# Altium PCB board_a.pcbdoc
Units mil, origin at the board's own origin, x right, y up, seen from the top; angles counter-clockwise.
Board outline 3937.01 x 4409.45 mil, 4 copper layers (Top Layer, In1.Cu, In2.Cu, Bottom Layer), stack 2.757 mil thick; 194 components, 98 nets, 535 pads, 281 vias.
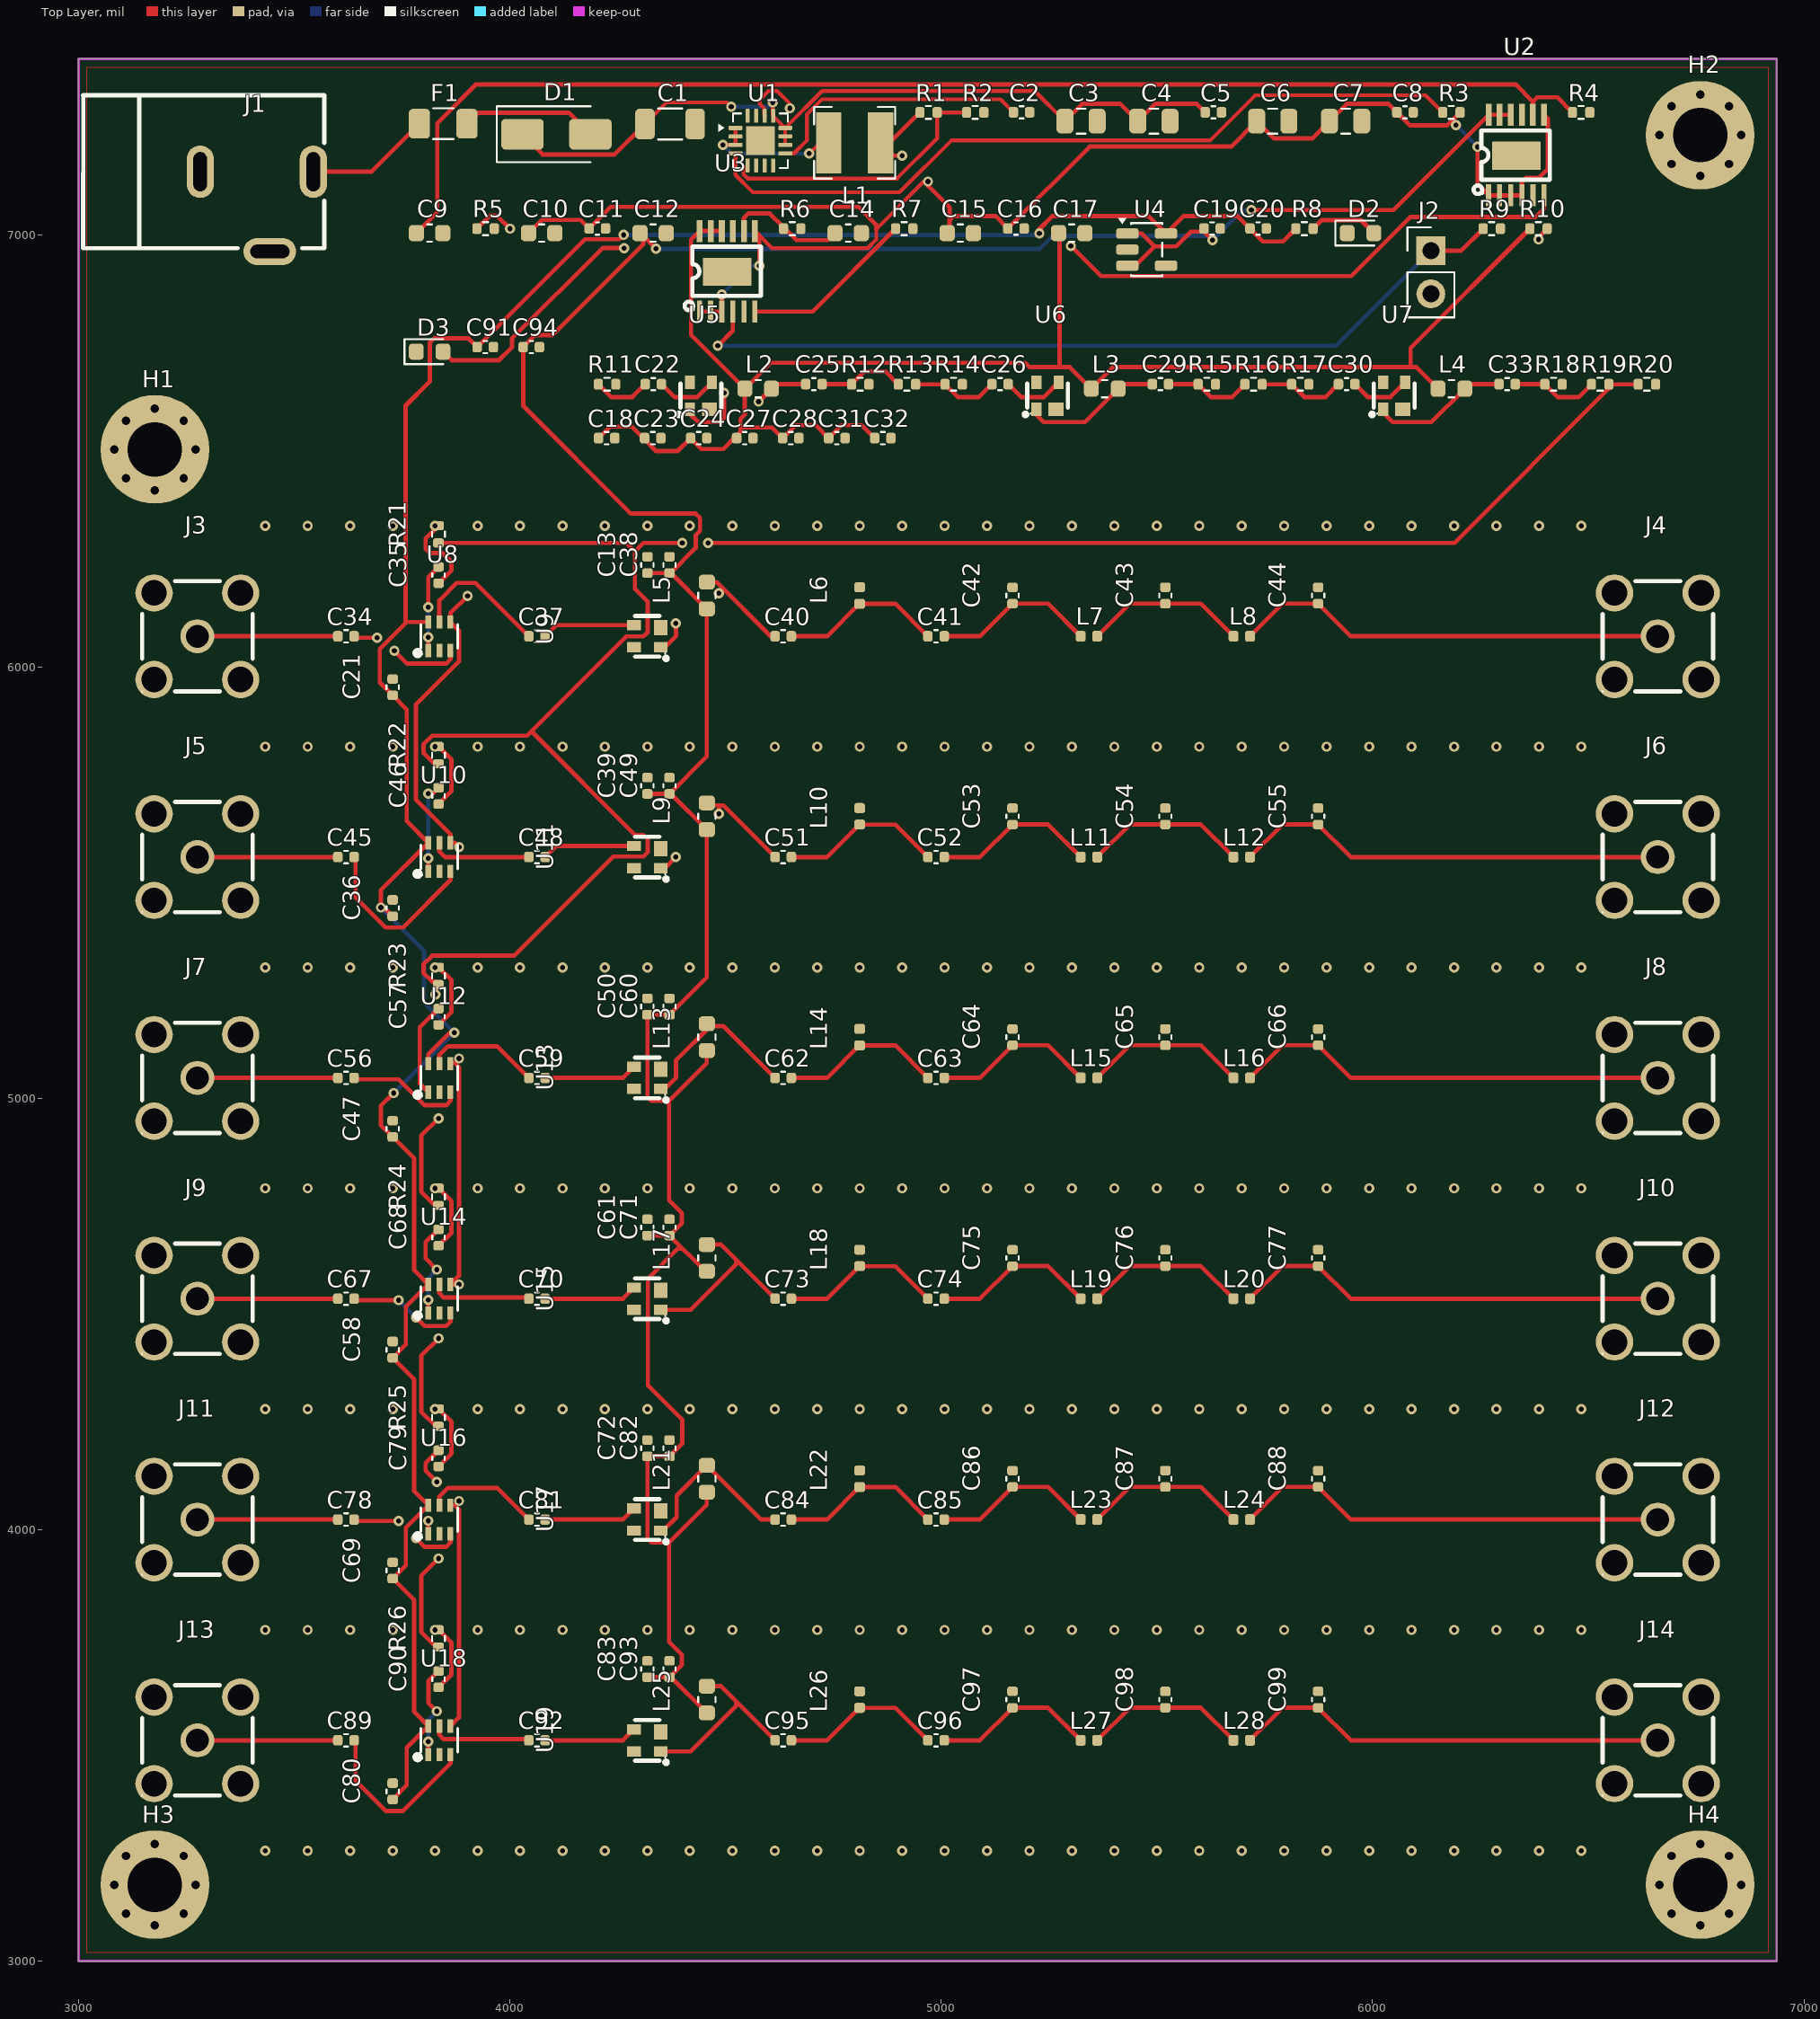
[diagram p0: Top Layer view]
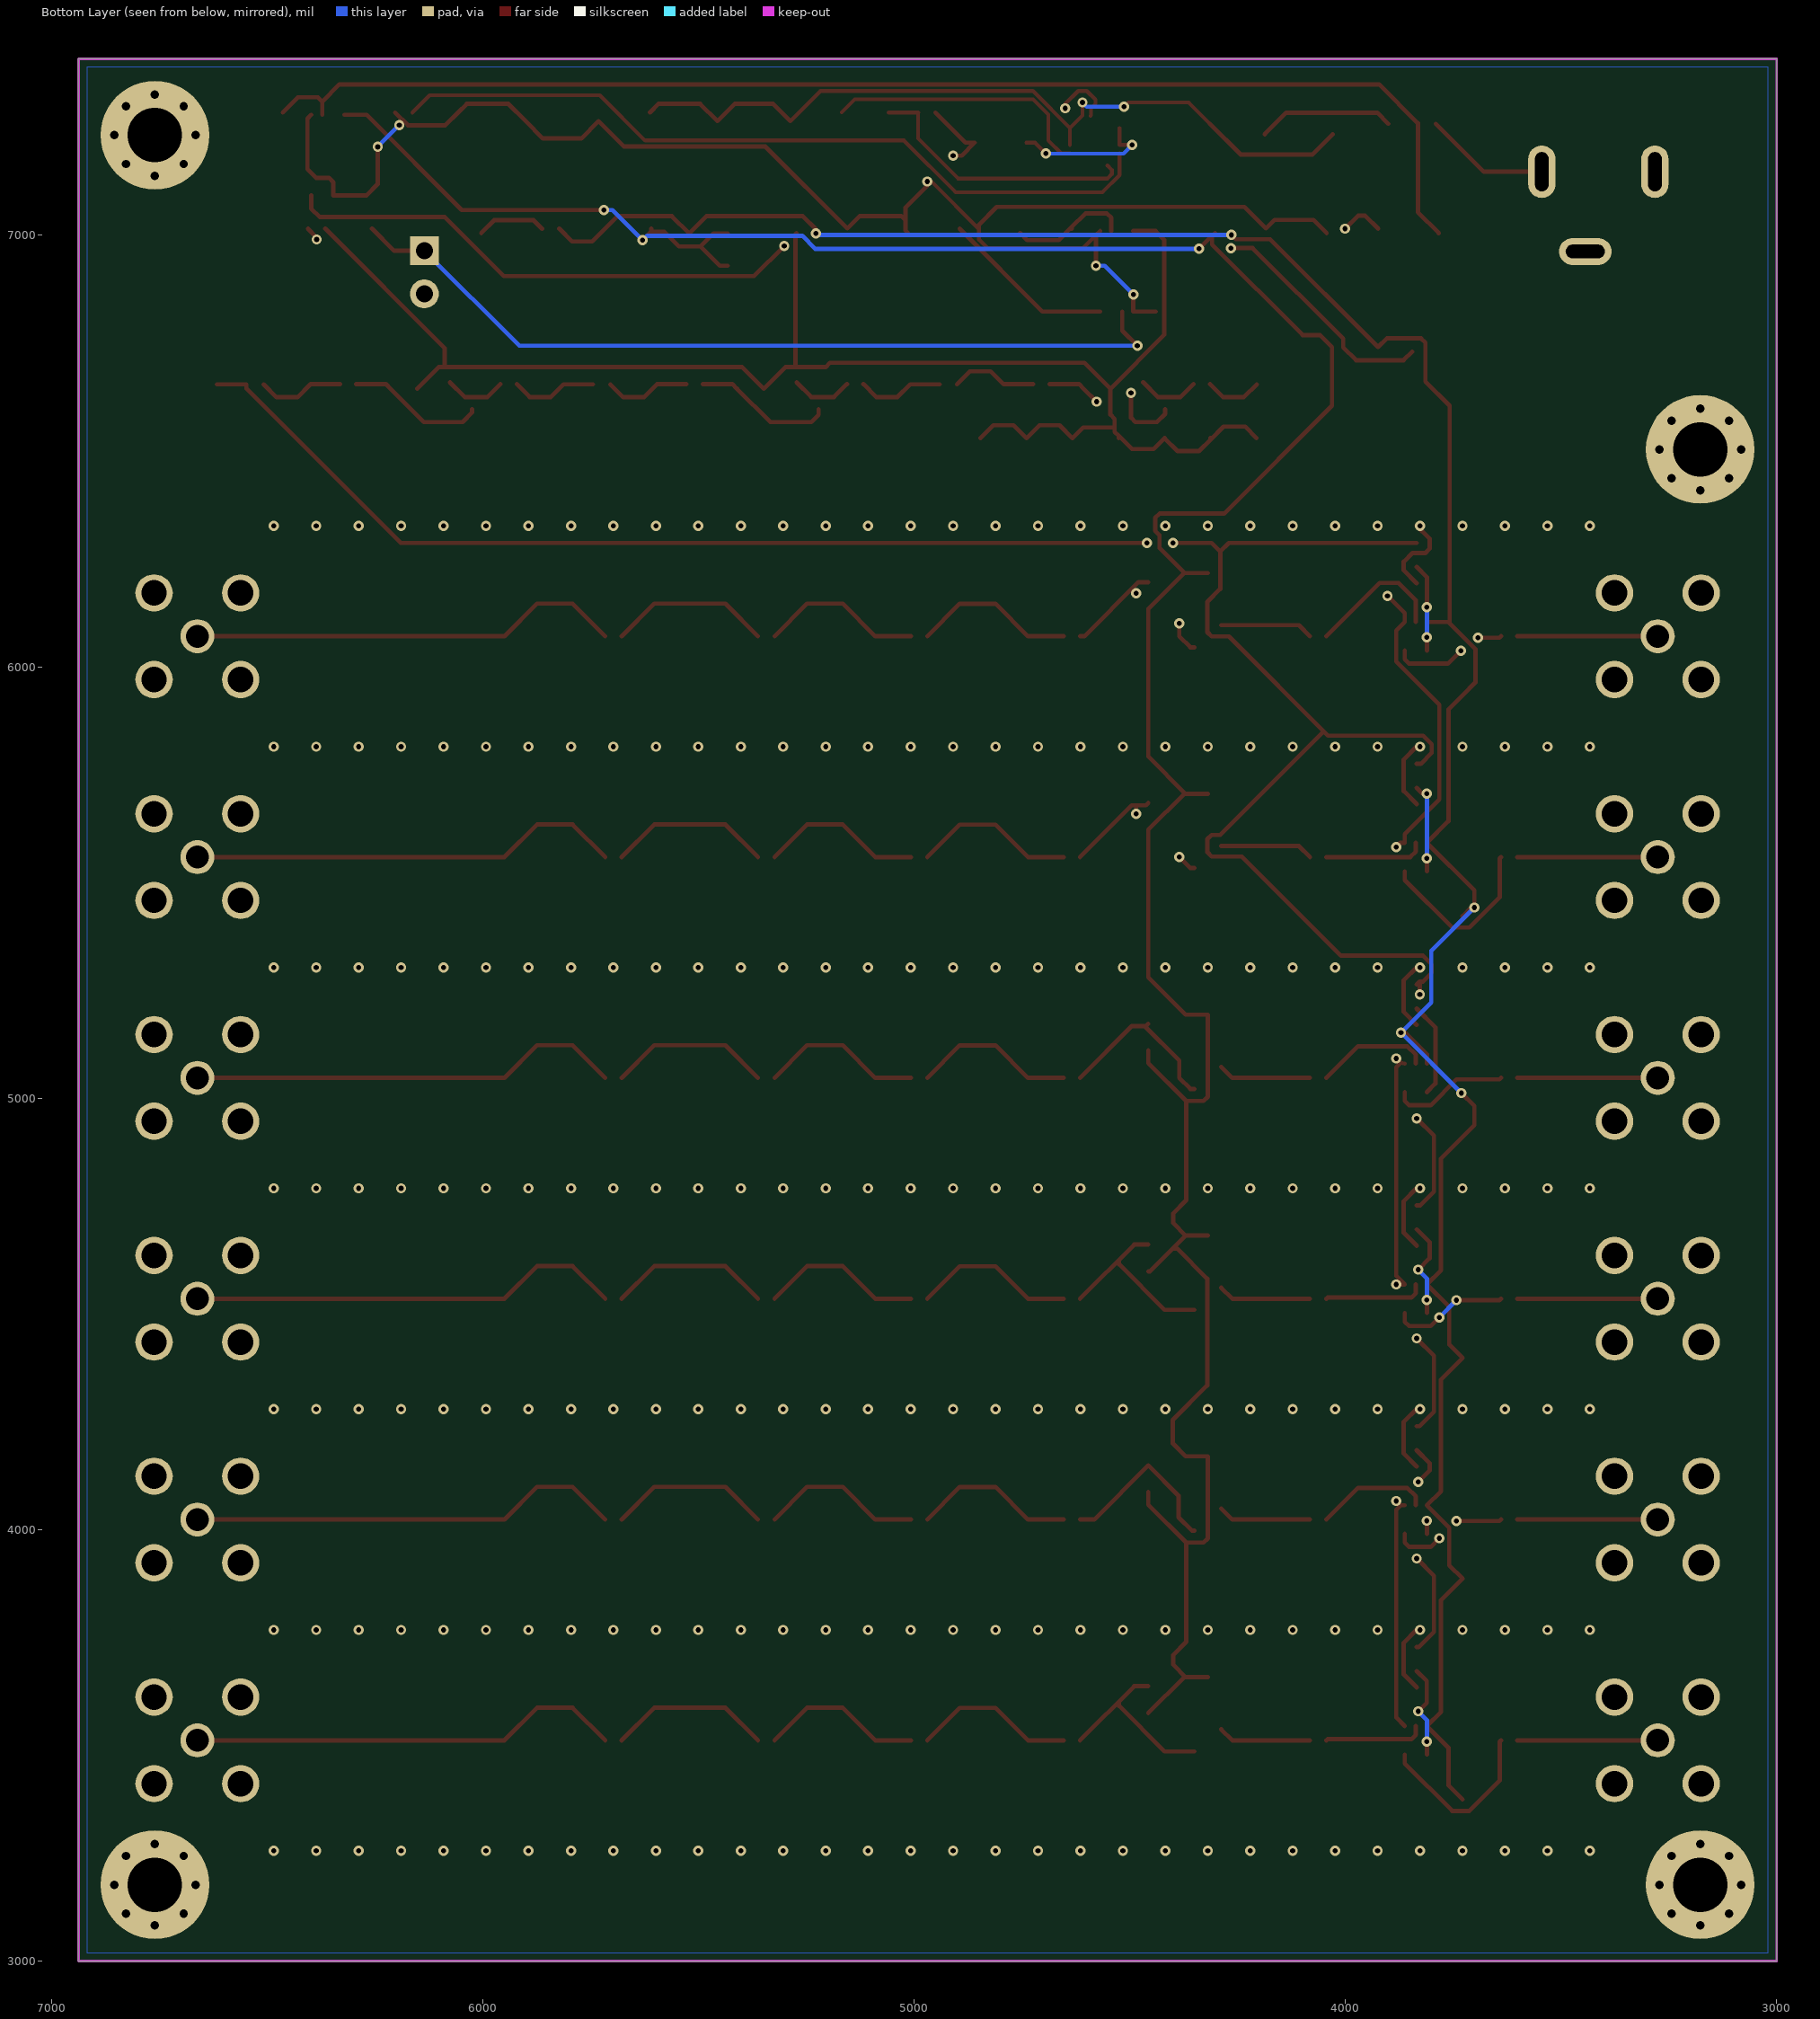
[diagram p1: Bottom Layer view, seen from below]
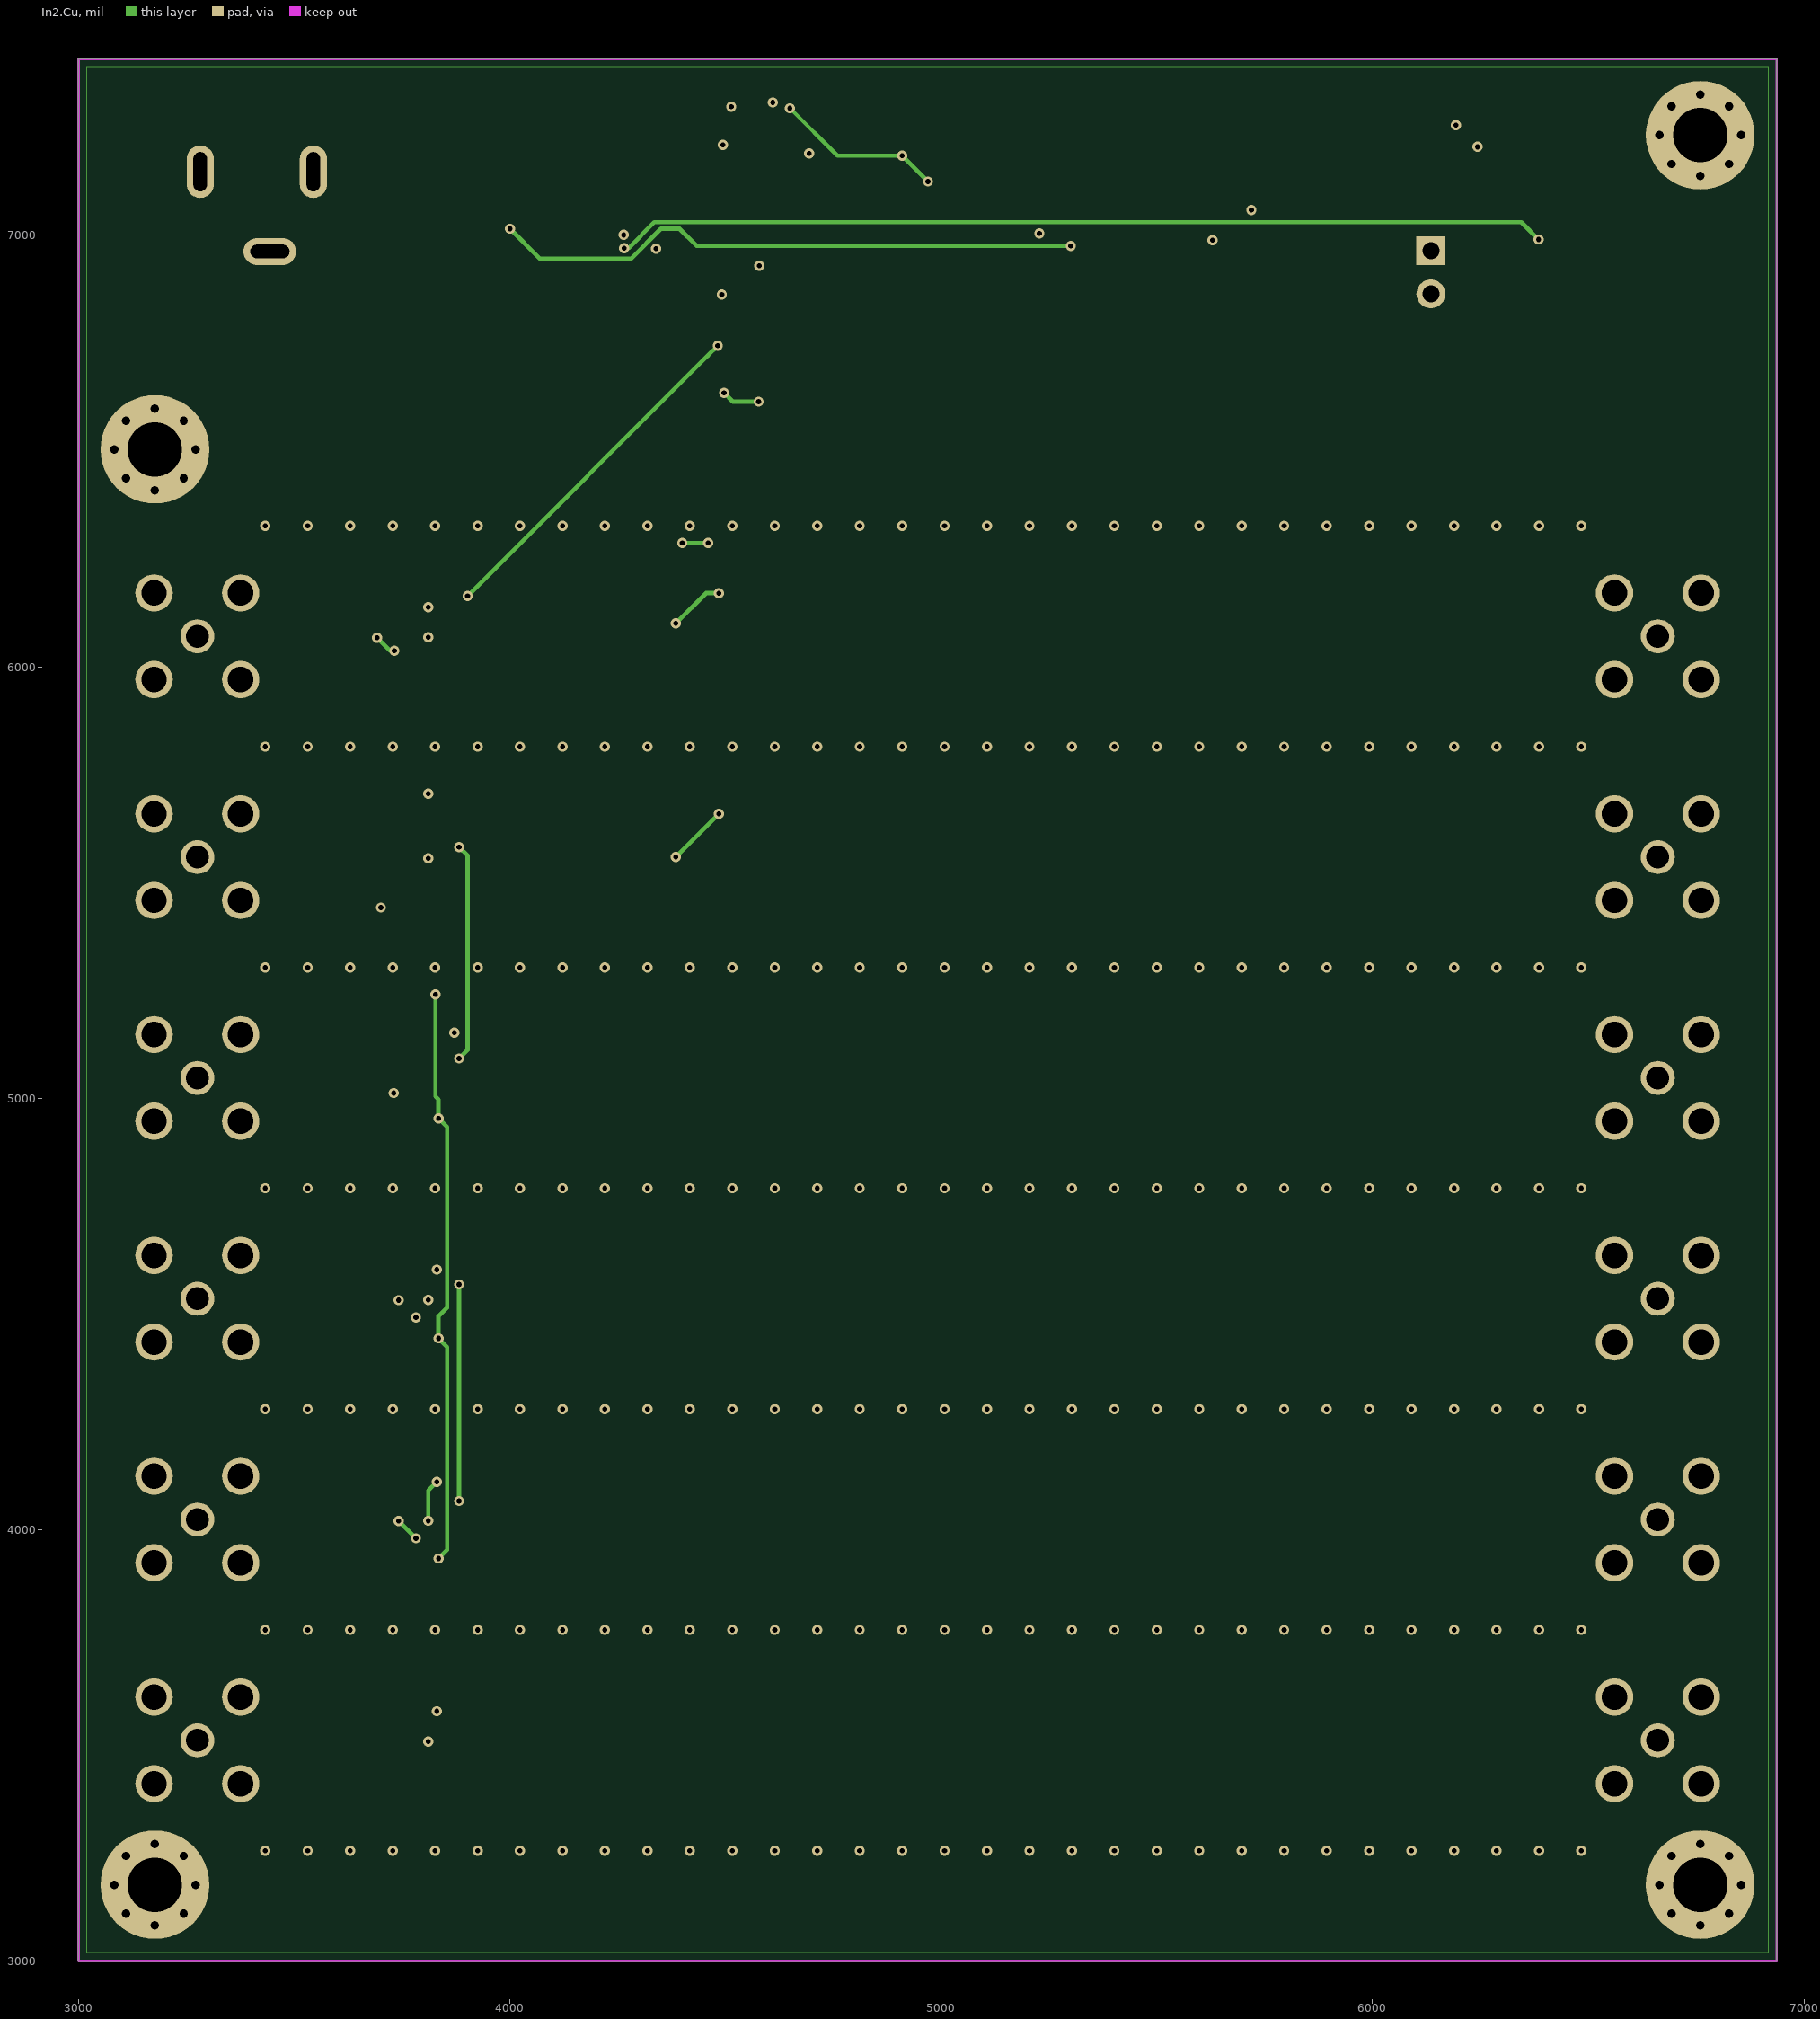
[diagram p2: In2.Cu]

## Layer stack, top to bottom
Top Solder Mask Layer: solder mask 0.394, Dk 3.3
Top Layer: signal copper 1.379
In1.Cu: signal copper (thickness not stored)
In2.Cu: signal copper (thickness not stored)
Bottom Layer: signal copper 1.378
Bottom Solder Mask Layer: solder mask 0.394, Dk 3.3

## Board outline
6937.01,3000 3000,3000 3000,7409.45 6937.01,7409.45

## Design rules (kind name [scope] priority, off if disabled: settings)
BoardOutlineClearance copperThickness1oz [All] p0: genericclearance=10 ignorepadtopadclearanceinfootprint=FALSE except(0: Arc-SplitContinuation Track-SplitContinuation SMDPad-SplitContinuation THPad-SplitContinuation Via-SplitContinuation Fill-SplitContinuation Poly-SplitContinuation Region-SplitContinuation Text-SplitContinuation)
BoardOutlineClearance otherClearance [All] p0: genericclearance=10 ignorepadtopadclearanceinfootprint=FALSE except(0: Arc-SplitContinuation Track-SplitContinuation SMDPad-SplitContinuation THPad-SplitContinuation Via-SplitContinuation Fill-SplitContinuation Poly-SplitContinuation Region-SplitContinuation Text-SplitContinuation)
Clearance copperThickness1oz [All] p1: gap=7 ignorepadtopadclearanceinfootprint=FALSE
Clearance otherClearance [All] p1: gap=7 ignorepadtopadclearanceinfootprint=FALSE
DiffPairsRouting differentialPair [All] p1: maxuncoupledlength=10 minlimit=5 maxlimit=Infinity mostfreqgap=6 toplayer_minwidth=5 toplayer_prefwidth=100 toplayer_maxwidth=100 bottomlayer_minwidth=5 bottomlayer_prefwidth=100 bottomlayer_maxwidth=100 midlayer1_minwidth=5 midlayer1_prefwidth=100 midlayer1_maxwidth=100 midlayer2_minwidth=5 midlayer2_prefwidth=100 midlayer2_maxwidth=100
PasteMaskExpansion pad_to_mask_clearance [All] p1: expansion=0
PlaneConnect innerPlane [All] p1: planeconnectstyle=Relief reliefexpansion=20 reliefentries=4 reliefconductorwidth=10 reliefairgap=10
PolygonConnect copper0 [All] p1: connectstyle=Relief reliefentries=4 reliefconductorwidth=11.811 polygonreliefangle="90 Angle" airgapwidth=9.8425
RoutingVias viaSize [All] p1: viastyle="Through Hole" holewidth=11.811 minholewidth=7.874 maxholewidth=236.2204 width=11.811 minwidth=7.874 maxwidth=236.2204
SolderMaskExpansion pad_to_mask_clearance [IsVia] p1: useseparateexpansions=TRUE expansion=-1000 expansionbottom=-1000
SolderMaskExpansion pad_to_mask_clearance [All] p2: useseparateexpansions=TRUE expansion=0 expansionbottom=0
Width copperThickness1oz [All] p1: maxlimit=100 minlimit=5 preferedwidth=10

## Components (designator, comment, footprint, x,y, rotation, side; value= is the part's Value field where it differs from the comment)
C1 "22u" Capacitor_SMD:C_1206_3216Metric 4371.46,7258.07 r0 top
C2 "3.3n" Capacitor_SMD:C_0402_1005Metric 5186.42,7285.24 r0 top
C3 "10u" Capacitor_SMD:C_0805_2012Metric 5324.21,7264.76 r0 top
C4 "10u" Capacitor_SMD:C_0805_2012Metric 5493.11,7264.76 r0 top
C5 "100n" Capacitor_SMD:C_0402_1005Metric 5630.91,7285.24 r0 top
C6 "22u" Capacitor_SMD:C_0805_2012Metric 5768.7,7264.76 r0 top
C7 "22u" Capacitor_SMD:C_0805_2012Metric 5937.6,7264.76 r0 top
C8 "100n" Capacitor_SMD:C_0402_1005Metric 6075.39,7285.24 r0 top
C9 "4.7u" Capacitor_SMD:C_0603_1608Metric 3813.98,7005.31 r0 top
C10 "10u" Capacitor_SMD:C_0603_1608Metric 4073.82,7005.31 r0 top
C11 "100n" Capacitor_SMD:C_0402_1005Metric 4202.95,7015.94 r0 top
C12 "10u" Capacitor_SMD:C_0603_1608Metric 4332.09,7005.31 r0 top
C13 "100n" Capacitor_SMD:C_0402_1005Metric 4318.9,6236.22 r90 top
C14 "4.7u" Capacitor_SMD:C_0603_1608Metric 4784.45,7005.31 r0 top
C15 "10u" Capacitor_SMD:C_0603_1608Metric 5044.29,7005.31 r0 top
C16 "100n" Capacitor_SMD:C_0402_1005Metric 5173.43,7015.94 r0 top
C17 "10u" Capacitor_SMD:C_0603_1608Metric 5302.56,7005.31 r0 top
C18 "100n" Capacitor_SMD:C_0402_1005Metric 4224.61,6530.12 r0 top
C19 "1u" Capacitor_SMD:C_0402_1005Metric 5628.15,7015.94 r0 top
C20 "1u" Capacitor_SMD:C_0402_1005Metric 5734.84,7015.94 r0 top
C21 "100n" Capacitor_SMD:C_0402_1005Metric 3728.35,5952.76 r90 top
C22 "100p" Capacitor_SMD:C_0402_1005Metric 4332.87,6655.31 r0 top
C23 "100p" Capacitor_SMD:C_0402_1005Metric 4331.3,6530.12 r0 top
C24 "100n" Capacitor_SMD:C_0402_1005Metric 4437.99,6530.12 r0 top
C25 "100p" Capacitor_SMD:C_0402_1005Metric 4704.92,6655.31 r0 top
C26 "100p" Capacitor_SMD:C_0402_1005Metric 5136.42,6655.31 r0 top
C27 "100p" Capacitor_SMD:C_0402_1005Metric 4544.69,6530.12 r0 top
C28 "100n" Capacitor_SMD:C_0402_1005Metric 4651.38,6530.12 r0 top
C29 "100p" Capacitor_SMD:C_0402_1005Metric 5508.46,6655.31 r0 top
C30 "100p" Capacitor_SMD:C_0402_1005Metric 5939.96,6655.31 r0 top
C31 "100p" Capacitor_SMD:C_0402_1005Metric 4758.07,6530.12 r0 top
C32 "100n" Capacitor_SMD:C_0402_1005Metric 4864.76,6530.12 r0 top
C33 "100p" Capacitor_SMD:C_0402_1005Metric 6312.01,6655.31 r0 top
C34 "100p" Capacitor_SMD:C_0402_1005Metric 3620.08,6070.87 r0 top
C35 "100p" Capacitor_SMD:C_0402_1005Metric 3834.65,6212.6 r90 top
C36 "100p" Capacitor_SMD:C_0402_1005Metric 3728.35,5440.94 r90 top
C37 "100p" Capacitor_SMD:C_0402_1005Metric 4062.99,6070.87 r0 top
C38 "100p" Capacitor_SMD:C_0402_1005Metric 4370.08,6236.22 r90 top
C39 "100n" Capacitor_SMD:C_0402_1005Metric 4318.9,5724.41 r90 top
C40 "7.5p" Capacitor_SMD:C_0402_1005Metric 4633.86,6070.87 r0 top
C41 "7.5p" Capacitor_SMD:C_0402_1005Metric 4988.19,6070.87 r0 top
C42 "4.7p" Capacitor_SMD:C_0402_1005Metric 5165.35,6165.35 r90 top
C43 "8.2p" Capacitor_SMD:C_0402_1005Metric 5519.69,6165.35 r90 top
C44 "4.7p" Capacitor_SMD:C_0402_1005Metric 5874.02,6165.35 r90 top
C45 "100p" Capacitor_SMD:C_0402_1005Metric 3620.08,5559.06 r0 top
C46 "100p" Capacitor_SMD:C_0402_1005Metric 3834.65,5700.79 r90 top
C47 "100p" Capacitor_SMD:C_0402_1005Metric 3728.35,4929.13 r90 top
C48 "100p" Capacitor_SMD:C_0402_1005Metric 4062.99,5559.06 r0 top
C49 "100p" Capacitor_SMD:C_0402_1005Metric 4370.08,5724.41 r90 top
C50 "100n" Capacitor_SMD:C_0402_1005Metric 4318.9,5212.6 r90 top
C51 "7.5p" Capacitor_SMD:C_0402_1005Metric 4633.86,5559.06 r0 top
C52 "7.5p" Capacitor_SMD:C_0402_1005Metric 4988.19,5559.06 r0 top
C53 "4.7p" Capacitor_SMD:C_0402_1005Metric 5165.35,5653.54 r90 top
C54 "8.2p" Capacitor_SMD:C_0402_1005Metric 5519.69,5653.54 r90 top
C55 "4.7p" Capacitor_SMD:C_0402_1005Metric 5874.02,5653.54 r90 top
C56 "100p" Capacitor_SMD:C_0402_1005Metric 3620.08,5047.24 r0 top
C57 "100p" Capacitor_SMD:C_0402_1005Metric 3834.65,5188.98 r90 top
C58 "100p" Capacitor_SMD:C_0402_1005Metric 3728.35,4417.32 r90 top
C59 "100p" Capacitor_SMD:C_0402_1005Metric 4062.99,5047.24 r0 top
C60 "100p" Capacitor_SMD:C_0402_1005Metric 4370.08,5212.6 r90 top
C61 "100n" Capacitor_SMD:C_0402_1005Metric 4318.9,4700.79 r90 top
C62 "7.5p" Capacitor_SMD:C_0402_1005Metric 4633.86,5047.24 r0 top
C63 "7.5p" Capacitor_SMD:C_0402_1005Metric 4988.19,5047.24 r0 top
C64 "4.7p" Capacitor_SMD:C_0402_1005Metric 5165.35,5141.73 r90 top
C65 "8.2p" Capacitor_SMD:C_0402_1005Metric 5519.69,5141.73 r90 top
C66 "4.7p" Capacitor_SMD:C_0402_1005Metric 5874.02,5141.73 r90 top
C67 "100p" Capacitor_SMD:C_0402_1005Metric 3620.08,4535.43 r0 top
C68 "100p" Capacitor_SMD:C_0402_1005Metric 3834.65,4677.17 r90 top
C69 "100p" Capacitor_SMD:C_0402_1005Metric 3728.35,3905.51 r90 top
C70 "100p" Capacitor_SMD:C_0402_1005Metric 4062.99,4535.43 r0 top
C71 "100p" Capacitor_SMD:C_0402_1005Metric 4370.08,4700.79 r90 top
C72 "100n" Capacitor_SMD:C_0402_1005Metric 4318.9,4188.98 r90 top
C73 "7.5p" Capacitor_SMD:C_0402_1005Metric 4633.86,4535.43 r0 top
C74 "7.5p" Capacitor_SMD:C_0402_1005Metric 4988.19,4535.43 r0 top
C75 "4.7p" Capacitor_SMD:C_0402_1005Metric 5165.35,4629.92 r90 top
C76 "8.2p" Capacitor_SMD:C_0402_1005Metric 5519.69,4629.92 r90 top
C77 "4.7p" Capacitor_SMD:C_0402_1005Metric 5874.02,4629.92 r90 top
C78 "100p" Capacitor_SMD:C_0402_1005Metric 3620.08,4023.62 r0 top
C79 "100p" Capacitor_SMD:C_0402_1005Metric 3834.65,4165.35 r90 top
C80 "100p" Capacitor_SMD:C_0402_1005Metric 3728.35,3393.7 r90 top
C81 "100p" Capacitor_SMD:C_0402_1005Metric 4062.99,4023.62 r0 top
C82 "100p" Capacitor_SMD:C_0402_1005Metric 4370.08,4188.98 r90 top
C83 "100n" Capacitor_SMD:C_0402_1005Metric 4318.9,3677.17 r90 top
C84 "7.5p" Capacitor_SMD:C_0402_1005Metric 4633.86,4023.62 r0 top
C85 "7.5p" Capacitor_SMD:C_0402_1005Metric 4988.19,4023.62 r0 top
C86 "4.7p" Capacitor_SMD:C_0402_1005Metric 5165.35,4118.11 r90 top
C87 "8.2p" Capacitor_SMD:C_0402_1005Metric 5519.69,4118.11 r90 top
C88 "4.7p" Capacitor_SMD:C_0402_1005Metric 5874.02,4118.11 r90 top
C89 "100p" Capacitor_SMD:C_0402_1005Metric 3620.08,3511.81 r0 top
C90 "100p" Capacitor_SMD:C_0402_1005Metric 3834.65,3653.54 r90 top
C91 "100p" Capacitor_SMD:C_0402_1005Metric 3943.11,6741.14 r0 top
C92 "100p" Capacitor_SMD:C_0402_1005Metric 4062.99,3511.81 r0 top
C93 "100p" Capacitor_SMD:C_0402_1005Metric 4370.08,3677.17 r90 top
C94 "100n" Capacitor_SMD:C_0402_1005Metric 4049.8,6741.14 r0 top
C95 "7.5p" Capacitor_SMD:C_0402_1005Metric 4633.86,3511.81 r0 top
C96 "7.5p" Capacitor_SMD:C_0402_1005Metric 4988.19,3511.81 r0 top
C97 "4.7p" Capacitor_SMD:C_0402_1005Metric 5165.35,3606.3 r90 top
C98 "8.2p" Capacitor_SMD:C_0402_1005Metric 5519.69,3606.3 r90 top
C99 "4.7p" Capacitor_SMD:C_0402_1005Metric 5874.02,3606.3 r90 top
D1 "SS34" Diode_SMD:D_SMA 4108.07,7234.45 r0 top
D2 "green" LED_SMD:LED_0603_1608Metric 5972.24,7005.31 r0 top
D3 "yellow" LED_SMD:LED_0603_1608Metric 3813.98,6730.51 r0 top
F1 "1.5A" Fuse:Fuse_1206_3216Metric 3845.47,7258.86 r0 top
H1 "M3" MountingHole:MountingHole_3.2mm_M3_Pad_Via 3177.17,6503.94 r0 top
H2 "M3" MountingHole:MountingHole_3.2mm_M3_Pad_Via 6759.84,7232.28 r0 top
H3 "M3" MountingHole:MountingHole_3.2mm_M3_Pad_Via 3177.17,3177.17 r0 top
H4 "M3" MountingHole:MountingHole_3.2mm_M3_Pad_Via 6759.84,3177.17 r0 top
J1 "12V DC" prc:DC-IN-TH_DC-005C-20A 3413.39,7055.12 r0 top
J2 "CAL_EN" Connector_PinHeader_2.54mm:PinHeader_1x02_P2.54mm_Vertical 6135.24,6964.37 r0 top
J3 "ANT0" prc:SMA-TH_BWSMA-KE-Z001 3275.59,6070.87 r0 top
J4 "OUT0" prc:SMA-TH_BWSMA-KE-Z001 6661.42,6070.87 r0 top
J5 "ANT1" prc:SMA-TH_BWSMA-KE-Z001 3275.59,5559.06 r0 top
J6 "OUT1" prc:SMA-TH_BWSMA-KE-Z001 6661.42,5559.06 r0 top
J7 "ANT2" prc:SMA-TH_BWSMA-KE-Z001 3275.59,5047.24 r0 top
J8 "OUT2" prc:SMA-TH_BWSMA-KE-Z001 6661.42,5047.24 r0 top
J9 "ANT3" prc:SMA-TH_BWSMA-KE-Z001 3275.59,4535.43 r0 top
J10 "OUT3" prc:SMA-TH_BWSMA-KE-Z001 6661.42,4535.43 r0 top
J11 "ANT4" prc:SMA-TH_BWSMA-KE-Z001 3275.59,4023.62 r0 top
J12 "OUT4" prc:SMA-TH_BWSMA-KE-Z001 6661.42,4023.62 r0 top
J13 "ANT5" prc:SMA-TH_BWSMA-KE-Z001 3275.59,3511.81 r0 top
J14 "OUT5" prc:SMA-TH_BWSMA-KE-Z001 6661.42,3511.81 r0 top
L1 "2.2u" Inductor_SMD:L_Bourns-SRN4018 4799.41,7214.76 r0 top
L2 "220n" Inductor_SMD:L_0603_1608Metric 4575.79,6644.69 r0 top
L3 "220n" Inductor_SMD:L_0603_1608Metric 5379.33,6644.69 r0 top
L4 "220n" Inductor_SMD:L_0603_1608Metric 6182.87,6644.69 r0 top
L5 "220n" Inductor_SMD:L_0603_1608Metric 4456.69,6165.35 r90 top
L6 "15n" Inductor_SMD:L_0402_1005Metric 4811.02,6165.35 r90 top
L7 "15n" Inductor_SMD:L_0402_1005Metric 5342.52,6070.87 r0 top
L8 "15n" Inductor_SMD:L_0402_1005Metric 5696.85,6070.87 r0 top
L9 "220n" Inductor_SMD:L_0603_1608Metric 4456.69,5653.54 r90 top
L10 "15n" Inductor_SMD:L_0402_1005Metric 4811.02,5653.54 r90 top
L11 "15n" Inductor_SMD:L_0402_1005Metric 5342.52,5559.06 r0 top
L12 "15n" Inductor_SMD:L_0402_1005Metric 5696.85,5559.06 r0 top
L13 "220n" Inductor_SMD:L_0603_1608Metric 4456.69,5141.73 r90 top
L14 "15n" Inductor_SMD:L_0402_1005Metric 4811.02,5141.73 r90 top
L15 "15n" Inductor_SMD:L_0402_1005Metric 5342.52,5047.24 r0 top
L16 "15n" Inductor_SMD:L_0402_1005Metric 5696.85,5047.24 r0 top
L17 "220n" Inductor_SMD:L_0603_1608Metric 4456.69,4629.92 r90 top
L18 "15n" Inductor_SMD:L_0402_1005Metric 4811.02,4629.92 r90 top
L19 "15n" Inductor_SMD:L_0402_1005Metric 5342.52,4535.43 r0 top
L20 "15n" Inductor_SMD:L_0402_1005Metric 5696.85,4535.43 r0 top
L21 "220n" Inductor_SMD:L_0603_1608Metric 4456.69,4118.11 r90 top
L22 "15n" Inductor_SMD:L_0402_1005Metric 4811.02,4118.11 r90 top
L23 "15n" Inductor_SMD:L_0402_1005Metric 5342.52,4023.62 r0 top
L24 "15n" Inductor_SMD:L_0402_1005Metric 5696.85,4023.62 r0 top
L25 "220n" Inductor_SMD:L_0603_1608Metric 4456.69,3606.3 r90 top
L26 "15n" Inductor_SMD:L_0402_1005Metric 4811.02,3606.3 r90 top
L27 "15n" Inductor_SMD:L_0402_1005Metric 5342.52,3511.81 r0 top
L28 "15n" Inductor_SMD:L_0402_1005Metric 5696.85,3511.81 r0 top
R1 "600k" Resistor_SMD:R_0402_1005Metric 4970.67,7284.84 r0 top
R2 "100k" Resistor_SMD:R_0402_1005Metric 5078.94,7284.84 r0 top
R3 "100k" Resistor_SMD:R_0402_1005Metric 6182.87,7284.84 r0 top
R4 "50.0k" Resistor_SMD:R_0402_1005Metric 6483.66,7284.84 r0 top
R5 "300" Resistor_SMD:R_0402_1005Metric 3943.9,7015.55 r0 top
R6 "50.0k" Resistor_SMD:R_0402_1005Metric 4654.53,7015.55 r0 top
R7 "300" Resistor_SMD:R_0402_1005Metric 4914.37,7015.55 r0 top
R8 "4.7k" Resistor_SMD:R_0402_1005Metric 5842.32,7015.55 r0 top
R9 "100k" Resistor_SMD:R_0402_1005Metric 6276.57,7015.55 r0 top
R10 "4.7k" Resistor_SMD:R_0402_1005Metric 6384.84,7015.55 r0 top
R11 "49.9" Resistor_SMD:R_0402_1005Metric 4225.39,6654.92 r0 top
R12 "294" Resistor_SMD:R_0402_1005Metric 4812.4,6654.92 r0 top
R13 "17.8" Resistor_SMD:R_0402_1005Metric 4920.67,6654.92 r0 top
R14 "294" Resistor_SMD:R_0402_1005Metric 5028.94,6654.92 r0 top
R15 "294" Resistor_SMD:R_0402_1005Metric 5615.94,6654.92 r0 top
R16 "17.8" Resistor_SMD:R_0402_1005Metric 5724.21,6654.92 r0 top
R17 "294" Resistor_SMD:R_0402_1005Metric 5832.48,6654.92 r0 top
R18 "294" Resistor_SMD:R_0402_1005Metric 6419.49,6654.92 r0 top
R19 "17.8" Resistor_SMD:R_0402_1005Metric 6527.76,6654.92 r0 top
R20 "294" Resistor_SMD:R_0402_1005Metric 6636.02,6654.92 r0 top
R21 "35.7" Resistor_SMD:R_0402_1005Metric 3834.65,6307.09 r90 top
R22 "35.7" Resistor_SMD:R_0402_1005Metric 3834.65,5795.28 r90 top
R23 "35.7" Resistor_SMD:R_0402_1005Metric 3834.65,5283.46 r90 top
R24 "35.7" Resistor_SMD:R_0402_1005Metric 3834.65,4771.65 r90 top
R25 "35.7" Resistor_SMD:R_0402_1005Metric 3834.65,4259.84 r90 top
R26 "35.7" Resistor_SMD:R_0402_1005Metric 3834.65,3748.03 r90 top
U1 "TPS62130RGTR" Package_DFN_QFN:VQFN-16-1EP_3x3mm_P0.5mm_EP1.68x1.68mm 4580.91,7219.49 r0 top
U2 "LT3045EMSE" prc:MSOP-12_L4.0-W3.0-P0.65-LS4.9-BL-EP 6333.27,7186.22 r0 top
U3 "LT3045EMSE" prc:MSOP-12_L4.0-W3.0-P0.65-LS4.9-BL-EP 4504.13,6916.93 r0 top
U4 "TLV75533PDBVR" Package_TO_SOT_SMD:SOT-23-5 5476.57,6967.13 r0 top
U5 "SPF5043Z" prc:SOT343_L2.0-W1.3-P1.30-LS2.1-BL 4443.11,6628.35 r0 top
U6 "SPF5043Z" prc:SOT343_L2.0-W1.3-P1.30-LS2.1-BL 5246.65,6628.35 r0 top
U7 "SPF5043Z" prc:SOT343_L2.0-W1.3-P1.30-LS2.1-BL 6050.2,6628.35 r0 top
U8 "PE4259-63" prc:SC-70-6_L2.2-W1.3-P0.65-LS2.1-BL 3836.61,6070.87 r0 top
U9 "SPF5043Z" prc:SOT343_L2.0-W1.3-P1.30-LS2.1-BL 4318.9,6070.87 r90 top
U10 "PE4259-63" prc:SC-70-6_L2.2-W1.3-P0.65-LS2.1-BL 3836.61,5559.06 r0 top
U11 "SPF5043Z" prc:SOT343_L2.0-W1.3-P1.30-LS2.1-BL 4318.9,5559.06 r90 top
U12 "PE4259-63" prc:SC-70-6_L2.2-W1.3-P0.65-LS2.1-BL 3836.61,5047.24 r0 top
U13 "SPF5043Z" prc:SOT343_L2.0-W1.3-P1.30-LS2.1-BL 4318.9,5047.24 r90 top
U14 "PE4259-63" prc:SC-70-6_L2.2-W1.3-P0.65-LS2.1-BL 3836.61,4535.43 r0 top
U15 "SPF5043Z" prc:SOT343_L2.0-W1.3-P1.30-LS2.1-BL 4318.9,4535.43 r90 top
U16 "PE4259-63" prc:SC-70-6_L2.2-W1.3-P0.65-LS2.1-BL 3836.61,4023.62 r0 top
U17 "SPF5043Z" prc:SOT343_L2.0-W1.3-P1.30-LS2.1-BL 4318.9,4023.62 r90 top
U18 "PE4259-63" prc:SC-70-6_L2.2-W1.3-P0.65-LS2.1-BL 3836.61,3511.81 r0 top
U19 "SPF5043Z" prc:SOT343_L2.0-W1.3-P1.30-LS2.1-BL 4318.9,3511.81 r90 top

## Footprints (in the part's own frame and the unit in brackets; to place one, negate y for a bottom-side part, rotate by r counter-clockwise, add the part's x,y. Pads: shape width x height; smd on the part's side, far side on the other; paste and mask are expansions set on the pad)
Capacitor_SMD:C_0402_1005Metric [mm]
  rrect50% 0.56x0.62 smd: 1(-0.48,0) 2(0.48,0)
  silkscreen extent -0.11,-0.36 0.11,0.36
Capacitor_SMD:C_0603_1608Metric [mm]
  rrect50% 0.9x0.95 smd: 1(-0.775,0) 2(0.775,0)
  silkscreen extent -0.14,-0.51 0.14,0.51
Capacitor_SMD:C_0805_2012Metric [mm]
  rrect50% 1x1.45 smd: 1(-0.95,0) 2(0.95,0)
  silkscreen extent -0.26,-0.73 0.26,0.73
Capacitor_SMD:C_1206_3216Metric [mm]
  rrect43% 1.15x1.8 smd: 1(-1.475,0) 2(1.475,0)
  silkscreen extent -0.71,-0.91 0.71,0.91
Connector_PinHeader_2.54mm:PinHeader_1x02_P2.54mm_Vertical [mm]
  rect 1.7x1.7 hole 1: 1(0,0)
  round 1.7 hole 1: 2(0,-2.54)
  silkscreen extent -1.38,-3.92 1.38,1.38
Diode_SMD:D_SMA [mm]
  rrect27% 2.5x1.8 smd: 1(-2,0) 2(2,0)
  silkscreen extent -3.51,-1.65 2,1.65
Fuse:Fuse_1206_3216Metric [mm]
  rrect40% 1.25x1.75 smd: 1(-1.4,0) 2(1.4,0)
  silkscreen extent -0.6,-0.91 0.6,0.91
Inductor_SMD:L_0402_1005Metric [mm]
  rrect50% 0.59x0.64 smd: 1(-0.485,0) 2(0.485,0)
Inductor_SMD:L_0603_1608Metric [mm]
  rrect50% 0.875x0.95 smd: 1(-0.787,0) 2(0.787,0)
  silkscreen extent -0.16,-0.51 0.16,0.51
Inductor_SMD:L_Bourns-SRN4018 [mm]
  rect 1.5x3.6 smd: 1(-1.525,0) 2(1.525,0)
  silkscreen extent -2.38,-2.11 2.39,2.11
LED_SMD:LED_0603_1608Metric [mm]
  rrect50% 0.875x0.95 smd: 1(-0.788,0) 2(0.787,0)
  silkscreen extent -1.49,-0.73 0.8,0.73
MountingHole:MountingHole_3.2mm_M3_Pad_Via [mm]
  round 0.8 hole 0.5: 1(-2.4,0) 1(-1.697,-1.697) 1(-1.697,1.697) 1(0,-2.4) 1(0,2.4) 1(1.697,-1.697) 1(1.697,1.697) 1(2.4,0)
  round 6.4 hole 3.2: 1(0,0)
Package_DFN_QFN:VQFN-16-1EP_3x3mm_P0.5mm_EP1.68x1.68mm [mm]
  rrect50% 0.825x0.25 smd: 1(-1.462,0.75) 2(-1.462,0.25) 3(-1.462,-0.25) 4(-1.462,-0.75) 9(1.463,-0.75) 10(1.463,-0.25) 11(1.463,0.25) 12(1.463,0.75)
  rrect50% 0.25x0.825 smd: 5(-0.75,-1.462) 6(-0.25,-1.462) 7(0.25,-1.462) 8(0.75,-1.462) 13(0.75,1.462) 14(0.25,1.462) 15(-0.25,1.462) 16(-0.75,1.462)
  rect 1.68x1.68 smd: 17(0,0)
  silkscreen extent -2.47,-1.61 1.61,1.61
Package_TO_SOT_SMD:SOT-23-5 [mm]
  rrect50% 1.325x0.6 smd: 1(-1.138,0.95) 2(-1.138,0) 3(-1.138,-0.95) 4(1.138,-0.95) 5(1.138,0.95)
  silkscreen extent -1.69,-1.56 0.91,1.84
prc:DC-IN-TH_DC-005C-20A [mm]
  oval 1.6x3.1 hole 0.8 slot 2.3 at 90 deg: 1(3.33,2.35) 2(-3.33,2.35)
  oval 3.1x1.6 hole 0.8 slot 2.3 at 0 deg: 3(0.77,-2.35)
  silkscreen extent -10.23,-2.15 4.01,6.88
prc:MSOP-12_L4.0-W3.0-P0.65-LS4.9-BL-EP [mm]
  rect 0.3x1.3 smd: 1(-1.63,-2.37) 2(-0.98,-2.37) 3(-0.32,-2.37) 4(0.33,-2.37) 5(0.98,-2.37) 6(1.63,-2.37)
  rect 0.35x1.3 smd: 7(1.63,2.37) 8(0.98,2.37) 9(0.33,2.37) 10(-0.32,2.37) 11(-0.98,2.37) 12(-1.63,2.37)
  rect 2.85x1.65 smd: 13(0,-0.04)
  silkscreen extent -2.51,-2.3 1.98,1.45
prc:SC-70-6_L2.2-W1.3-P0.65-LS2.1-BL [mm]
  rect 0.35x0.78 smd: 1(-0.65,-0.84) 2(0,-0.84) 3(0.65,-0.84) 4(0.65,0.84) 5(0,0.84) 6(-0.65,0.84)
  silkscreen extent -1.43,-1.14 1.08,0.7
prc:SMA-TH_BWSMA-KE-Z001 [mm]
  round 2.2 hole 1.5: 1(-2.55,-2.55) 2(-2.55,2.55) 3(2.55,2.55) 4(2.55,-2.55)
  round 2 hole 1.35: 5(0,0)
  silkscreen extent -3.28,-3.28 3.25,3.25
prc:SOT343_L2.0-W1.3-P1.30-LS2.1-BL [mm]
  rect 0.599x0.8 smd: 1(-0.65,-0.79) 3(0.65,0.79) 4(-0.65,0.79)
  rect 0.899x0.8 smd: 2(0.5,-0.79)
  silkscreen extent -1.4,-1.2 1.2,0.72
Resistor_SMD:R_0402_1005Metric [mm]
  rrect50% 0.54x0.64 smd: 1(-0.51,0) 2(0.51,0)
  silkscreen extent -0.15,-0.38 0.15,0.38

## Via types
v1: diameter 23.62, hole 11.8, Top Layer to Bottom Layer, 281 vias

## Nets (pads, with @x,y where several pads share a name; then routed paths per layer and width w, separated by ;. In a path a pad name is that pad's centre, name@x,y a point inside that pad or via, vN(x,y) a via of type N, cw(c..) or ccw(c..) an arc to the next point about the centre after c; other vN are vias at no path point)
+3V3: C20.1 C21.1 C36.1 C47.1 C58.1 C69.1 C80.1 C91.1 R8.1 U4.5 U8.6 U10.6 U12.6 U14.6 U16.6 U18.6 | length 6287.9
  Top Layer w10: C80.1 3761.02,3407.48 3761.02,3494.88 U18.6 3778.34,3577.56 3778.34,3836.61 C69.1 3759.01,3917.28 3759.01,4004.68 U16.6 3778.34,4089.37 3778.34,4348.42 C58.1 3759.01,4429.09 3759.01,4516.5 U14.6 3778.34,4601.18 3778.34,4860.24 C47.1 3701.02,4937.56 3701.02,4982.13 v1(3731.02,5012.13) ; C36.1 3708.27,5442.13 v1(3701.02,5442.13) 3701.02,5482.13 U10.6 3761.02,5642.13 3761.02,5901.18 C21.1 3698.35,5963.86 3698.35,6041.26 3761.02,6103.94 U8.6 ; 3758.34,6101.26 3758.34,6605.28 3814.33,6661.26 3814.33,6751.26 3824.33,6761.26 3904.1,6761.26 C91.1 4174.21,6991.14 4254.21,6991.14 v1(4264.21,7001.14) ; U12.6 3811.02,5102.13 3861.02,5152.13 v1(3871.02,5152.13) ; v1(5227.59,7004.53) 5227.59,7014.53 5257.59,7044.53 5481.36,7044.53 U4.5 5561.36,7044.53 5687.36,7044.53 C20.1 5745.94,6985.95 5792.64,6985.95 R8.1
  Bottom Layer w10: v1(3701.02,5442.13) 3801.02,5342.13 3801.02,5222.13 3866.7,5156.45 v1(3871.02,5152.13) v1(3731.02,5012.13) ; v1(4264.21,7001.14) 5224.21,7001.14 v1(5227.59,7004.53)
+5V6: C6.1 C7.1 C8.1 C10.1 C11.1 C15.1 C16.1 L1.2 R1.1 R3.2 U1.14 U2.1 U2.2 U2.3 U2.4 U2.7 U3.1 U3.2 U3.3 U3.7 | length 4422.4
  Top Layer w8.89: U3.7 4608.31,6970.24 4829.45,6970.24 4849.45,6990.24 4849.45,7014.76 4959.45,7124.76 v1(4969.45,7124.76) ; U1.14 4589.45,7278.37 4589.45,7294.76 4579.45,7304.76 4579.45,7314.76 4599.45,7334.76 4619.45,7334.76 4649.45,7304.76 v1(4649.45,7294.76)
  Top Layer w10: C10.1 4073.94,7035.95 4164.06,7035.95 C11.1 4234.06,7065.95 4808.27,7065.95 4849.45,7024.76 4849.45,7014.76 ; U3.1 U3.2 U3.3 v1(4491.54,6862.88) ; U3.7 4578.31,7000.24 v1(4578.31,6929.65) ; v1(4909.45,7184.76) 4889.45,7184.76 L1.2 4880.51,7214.76 R1.1 ; v1(4969.45,7124.76) 4969.45,7114.76 5019.45,7064.76 5019.45,7010.98 C15.1 ; 5019.45,7034.76 5029.45,7044.76 5125.71,7044.76 C16.1 5344.53,7205.95 5672.48,7205.95 C6.1 5771.3,7224.76 5860.2,7224.76 C7.1 5940.19,7304.76 6036.97,7304.76 C8.1 6086.5,7255.24 6173.35,7255.24 R3.2 ; 6183.35,7265.24 v1(6193.35,7255.24) ; v1(6243.35,7205.24) 6243.35,7118.66 U2.1 U2.2 U2.3 U2.4 6346.26,7123.5 6356.26,7133.5 6386.26,7133.5 6406.26,7153.5 6406.26,7270.71 U2.7
  In2.Cu w8.89: v1(4649.45,7294.76) 4759.45,7184.76 v1(4909.45,7184.76)
  In2.Cu w10: v1(4909.45,7184.76) v1(4969.45,7124.76)
  Bottom Layer w10: v1(4491.54,6862.88) 4558.31,6929.65 v1(4578.31,6929.65) ; v1(6193.35,7255.24) v1(6243.35,7205.24)
+5V_LNA: C12.1 C13.1 C19.1 C38.1 C39.1 C49.1 C50.1 C60.1 C61.1 C71.1 C72.1 C82.1 C83.1 C93.1 C94.1 L5.1 L9.1 L13.1 L17.1 L21.1 L25.1 U2.10 U2.11 U2.12 U4.1 U4.3 | length 7452.1
  Top Layer w10: C12.1 C12.1@4309.1,6998.94 ; C83.1 C93.1 ; C61.1 C71.1 ; C39.1 C49.1 ; C13.1 C38.1@4372.91,6217.32 ; v1(4339.1,6968.94) C12.1@4309.1,6998.94 ; 4400.08,4651.89 4390.08,4651.89 4320.08,4581.89 4320.08,4334.41 4400.08,4254.41 4400.08,4200.08 C82.1 C72.1 4318.9,3980.08 4328.9,3970.08 4368.9,3970.08 ; L25.1 4373.72,3658.27 C93.1 ; L21.1 4456.69,4057.87 4368.9,3970.08 ; L17.1 4453.05,4598.92 C71.1 ; L13.1 4456.69,5081.5 4368.9,4993.7 ; U4.3 5449.88,6929.73 5494.69,6974.53 ; U4.1 5464.69,7004.53 5494.69,6974.53 ; C19.1 C19.1@5609.1,7008.94 ; v1(5629.1,6988.94) C19.1@5609.1,7008.94 ; v1(5719.1,7058.94) 6048.51,7058.94 U2.12 U2.11 U2.10 ; C12.1@4309.1,6998.94 4309.1,6978.94 4099.1,6768.94 4058.7,6768.94 C94.1 4030.91,6605.31 4280.91,6355.31 4430.91,6355.31 4440.91,6345.31 4440.91,6315.31 4430.91,6305.31 4430.91,6275.31 C38.1@4372.91,6217.32 ; 4368.9,3970.08 4368.9,3740.08 4398.9,3710.08 4398.9,3687.09 C93.1 ; 4368.9,4993.7 4328.9,4993.7 4318.9,5003.7 C50.1 C60.1 4456.69,5280.32 L9.1 4373.72,5705.51 C49.1 ; 4368.9,4993.7 4368.9,4763.7 4398.9,4733.7 4398.9,4710.71 C71.1 ; C49.1 4456.69,5792.13 4456.69,6134.35 4373.72,6217.32 C38.1@4372.91,6217.32 ; 5494.69,6974.53 5544.69,6974.53 5579.1,7008.94 C19.1@5609.1,7008.94
  Bottom Layer w10: v1(4339.1,6968.94) 5229.1,6968.94 5259.1,6998.94 5619.1,6998.94 v1(5629.1,6988.94) 5659.1,7018.94 5699.1,7058.94 v1(5719.1,7058.94)
+5V_NS: C17.1 C18.1 C23.1 C24.1 C27.1 C28.1 C31.1 C32.1 L2.1 L3.1 L4.1 R10.1 U3.10 U3.11 U3.12 | length 3808.7
  Top Layer w10: C18.1 4232.4,6556.81 4282.4,6556.81 C23.1@4312.4,6526.81 ; C23.1 C23.1@4312.4,6526.81 ; U3.10 U3.11 U3.12 4419.96,6990.24 4419.96,6769.51 L2.1 ; C27.1 C27.1@4524.78,6534.69 ; 4534.78,6554.69 4607.91,6554.69 C28.1 4662.48,6560.12 4709.17,6560.12 C31.1 4769.17,6560.12 4815.87,6560.12 C32.1 ; C17.1 5274.78,7002.58 5274.78,6694.69 ; 6088.32,6694.69 6088.32,6739.11 R10.1 ; L4.1 6101.87,6694.69 5398.33,6694.69 L3.1 5298.33,6694.69 5204.78,6694.69 5194.78,6704.69 4604.78,6704.69 L2.1 ; C23.1@4312.4,6526.81 4339.1,6500.12 4389.1,6500.12 C24.1 4444.53,6504.69 4494.78,6504.69 C27.1@4524.78,6534.69 ; C27.1@4524.78,6534.69 4534.78,6544.69 4534.78,6574.69 4544.78,6584.69 L2.1
+12V: C1.1 C3.1 C4.1 C5.1 D1.1 U1.10 U1.11 U1.12 U1.13 | length 1863.9
  Top Layer w8.89: C1.1 4363.33,7308.01 4503.39,7308.01 v1(4513.39,7298.01) ; v1(4609.49,7308.01) 4609.49,7278.01 U1.13 U1.12 ; U1.10 U1.11 U1.12 ; C3.1 5216.81,7334.76 4724.23,7334.76 U1.12
  Top Layer w10: D1.1 4076.21,7187.58 4242.89,7187.58 C1.1 ; C3.1 5326.81,7304.76 5415.71,7304.76 C4.1 5495.71,7304.76 5592.48,7304.76 C5.1
  Bottom Layer w8.89: v1(4513.39,7298.01) 4599.49,7298.01 v1(4609.49,7308.01)
BUCK5V6_FB: R1.2 R2.1 U1.5 | length 644.3
  Top Layer w8.89: U1.5 4541.38,7151.91 4541.38,7141.91 4551.38,7131.91 4897.82,7131.91 4990.75,7224.84 R1.2
  Top Layer w10: R1.2 R2.1
BUCK5V6_SS: C2.1 U1.9 | length 628.5
  Top Layer w8.89: U1.9 4658.48,7189.96 4688.48,7219.96 4688.48,7279.96 4723.76,7315.24 5137.52,7315.24 C2.1
BUCK5V6_SW: L1.1 U1.1 U1.2 U1.3 | length 332.3
  Top Layer w8.89: v1(4494.25,7209.65) U1.3 U1.2 U1.1 ; v1(4694.25,7189.65) 4719.37,7214.76 L1.1
  Bottom Layer w8.89: v1(4494.25,7209.65) 4514.25,7189.65 v1(4694.25,7189.65)
CAL_EN: J2.1 R9.1 U3.4 U8.4 U10.4 U12.4 U14.4 U16.4 U18.4 | length 5623.5
  Top Layer w10: U18.4 3882.2,3564.88 3882.2,4046.69 3872.2,4056.69 ; U16.4 3872.2,4056.69 ; U12.4 3872.2,5082.13 ; v1(3882.2,4066.69) 3872.2,4056.69 ; v1(3882.2,4568.51) U14.4 3882.2,4588.51 3882.2,5072.13 3872.2,5082.13 ; v1(3882.2,5092.13) 3872.2,5082.13 ; v1(3882.2,5582.13) 3872.2,5592.13 U10.4 3862.2,5612.48 3782.2,5692.48 3782.2,5912.48 3882.2,6012.48 3882.2,6083.94 U8.4 3862.2,6124.29 v1(3902.2,6164.29) ; v1(4482.2,6744.29) 4517.13,6779.21 U3.4 ; J2.1 6205.32,6964.37 R9.1
  In2.Cu w10: v1(3882.2,4066.69) v1(3882.2,4568.51) ; v1(3882.2,5092.13) 3902.2,5112.13 3902.2,5562.13 v1(3882.2,5582.13) ; v1(3902.2,6164.29) 4458.98,6721.07 v1(4482.2,6744.29)
  Bottom Layer w10: v1(4482.2,6744.29) 5915.16,6744.29 J2.1
CH0_ANT: C34.1 J3.5 | length 325.6
  Top Layer w10: J3.5 C34.1
CH0_CAL: C35.1 R21.2 | length 200.7
  Top Layer w10: C35.1 3864.64,6223.7 3864.64,6243.7 3844.64,6263.7 3814.64,6263.7 3804.64,6273.7 3804.64,6297.16 R21.2
  other v1: 3826.77,6326.77
CH0_F0: C40.2 C41.1 L6.1 | length 379
  Top Layer w10: C40.2 4735.63,6070.86 L6.1 4893.9,6146.26 C41.1
CH0_F2: C41.2 C42.1 L7.1 | length 379
  Top Layer w10: C41.2 5089.76,6070.86 C42.1 5247.83,6146.46 L7.1
CH0_F4: C43.1 L7.2 L8.1 | length 378.8
  Top Layer w10: L7.2 5437.2,6146.46 C43.1 5602.16,6146.46 L8.1
CH0_F6: C44.1 J4.5 L8.2 | length 1008.1
  Top Layer w10: L8.2 5791.53,6146.46 C44.1 5949.6,6070.86 J4.5
CH0_LNA_IN: C37.2 U9.3 | length 216.5
  Top Layer w10: C37.2 4107.48,6096.46 U9.3
CH0_LNA_OUT: C40.1 L5.2 U9.1 | length 428.9
  Top Layer w10: U9.1 4359.37,6045.27 4384.96,6070.86 v1(4384.96,6100.86) ; L5.2 4479.47,6196.36 4604.96,6070.86 C40.1 ; v1(4484.96,6170.86) 4494.96,6180.86
  In2.Cu w10: v1(4384.96,6100.86) 4454.96,6170.86 v1(4484.96,6170.86)
CH0_SW_C: C37.1 U8.5 | length 325.5
  Top Layer w10: U8.5 3836.61,6154.29 3876.61,6194.29 3920.67,6194.29 C37.1
CH0_SW_RF1: C35.2 U8.1 | length 203.5
  Top Layer w10: U8.1 v1(3811.02,6068.15) ; v1(3811.02,6138.15) 3811.02,6207.87 C35.2
  Bottom Layer w10: v1(3811.02,6068.15) v1(3811.02,6138.15)
CH0_SW_RF2: C34.2 U8.3 | length 274
  Top Layer w10: C34.2 3642.4,6067.44 v1(3692.2,6067.44) ; v1(3732.2,6037.44) 3762.2,6007.44 3852.2,6007.44 3862.2,6017.44 U8.3
  In2.Cu w10: v1(3692.2,6067.44) 3722.2,6037.44 v1(3732.2,6037.44)
CH1_ANT: C45.1 J5.5 | length 325.6
  Top Layer w10: J5.5 C45.1
CH1_CAL: C46.1 R22.2 | length 158.3
  Top Layer w10: C46.1 3864.64,5711.89 3864.64,5785.35 R22.2
  other v1: 3826.77,5814.96
CH1_F0: C51.2 C52.1 L10.1 | length 379
  Top Layer w10: C51.2 4735.63,5559.05 L10.1 4893.9,5634.45 C52.1
CH1_F2: C52.2 C53.1 L11.1 | length 379
  Top Layer w10: C52.2 5089.76,5559.05 C53.1 5247.83,5634.65 L11.1
CH1_F4: C54.1 L11.2 L12.1 | length 378.8
  Top Layer w10: L11.2 5437.2,5634.65 C54.1 5602.16,5634.65 L12.1
CH1_F6: C55.1 J6.5 L12.2 | length 1008.1
  Top Layer w10: L12.2 5791.53,5634.65 C55.1 5949.6,5559.05 J6.5
CH1_LNA_IN: C48.2 U11.3 | length 216.5
  Top Layer w10: C48.2 4107.48,5584.65 U11.3
CH1_LNA_OUT: C51.1 L9.2 U11.1 | length 417.2
  Top Layer w10: U11.1 4359.37,5533.46 v1(4384.96,5559.05) ; L9.2 4462.19,5679.05 4494.96,5679.05 C51.1 ; v1(4484.96,5659.05) 4484.96,5679.05
  In2.Cu w10: v1(4384.96,5559.05) v1(4484.96,5659.05)
CH1_SW_C: C48.1 U10.5 | length 233.1
  Top Layer w10: U10.5 3836.61,5571.77 3849.33,5559.05 C48.1
CH1_SW_RF1: C46.2 U10.1 | length 209.5
  Top Layer w10: U10.1 v1(3811.02,5556.34) ; v1(3811.02,5706.34) 3821.3,5706.34 C46.2
  Bottom Layer w10: v1(3811.02,5556.34) v1(3811.02,5706.34)
CH1_SW_RF2: C45.2 U10.3 | length 409.7
  Top Layer w10: C45.2 3642.2,5555.83 3642.2,5465.63 3712.2,5395.63 3752.2,5395.63 3862.2,5505.63 U10.3
CH2_ANT: C56.1 J7.5 | length 325.6
  Top Layer w10: J7.5 C56.1
CH2_CAL: C57.1 R23.2 | length 158.3
  Top Layer w10: C57.1 3864.64,5200.08 3864.64,5273.54 R23.2
  other v1: 3826.77,5303.15
CH2_F0: C62.2 C63.1 L14.1 | length 379
  Top Layer w10: C62.2 4735.63,5047.24 L14.1 4893.9,5122.64 C63.1
CH2_F2: C63.2 C64.1 L15.1 | length 379
  Top Layer w10: C63.2 5089.76,5047.24 C64.1 5247.83,5122.84 L15.1
CH2_F4: C65.1 L15.2 L16.1 | length 378.8
  Top Layer w10: L15.2 5437.2,5122.84 C65.1 5602.16,5122.84 L16.1
CH2_F6: C66.1 J8.5 L16.2 | length 1008.1
  Top Layer w10: L16.2 5791.53,5122.84 C66.1 5949.6,5047.24 J8.5
CH2_LNA_IN: C59.2 U13.3 | length 216.5
  Top Layer w10: C59.2 4262.21,5047.24 U13.3
CH2_LNA_OUT: C62.1 L13.2 U13.1 | length 408.9
  Top Layer w10: U13.1 4359.37,5021.65 4384.96,5047.24 4384.96,5087.24 L13.2@4464.96,5167.24 ; L13.2 4462.19,5167.24 4494.96,5167.24 C62.1
CH2_SW_C: C59.1 U12.5 | length 266.5
  Top Layer w10: U12.5 3836.61,5100.67 3856.61,5120.67 3970.67,5120.67 C59.1
CH2_SW_RF1: C57.2 U12.1 | length 220.1
  Top Layer w10: U12.1 3791.02,5034.17 3791.02,5164.25 C57.2
CH2_SW_RF2: C56.2 U12.3 | length 274
  Top Layer w10: C56.2 3642.4,5043.82 3742.2,5043.82 3802.2,4983.82 3852.2,4983.82 3862.2,4993.82 U12.3
CH3_ANT: C67.1 J9.5 | length 325.6
  Top Layer w10: J9.5 C67.1
CH3_CAL: C68.1 R24.2 | length 158.3
  Top Layer w10: C68.1 3864.64,4688.27 3864.64,4761.73 R24.2
  other v1: 3826.77,4791.34
CH3_F0: C73.2 C74.1 L18.1 | length 379
  Top Layer w10: C73.2 4735.63,4535.43 L18.1 4893.9,4610.83 C74.1
CH3_F2: C74.2 C75.1 L19.1 | length 379
  Top Layer w10: C74.2 5089.76,4535.43 C75.1 5247.83,4611.03 L19.1
CH3_F4: C76.1 L19.2 L20.1 | length 378.8
  Top Layer w10: L19.2 5437.2,4611.03 C76.1 5602.16,4611.03 L20.1
CH3_F6: C77.1 J10.5 L20.2 | length 1008.1
  Top Layer w10: L20.2 5791.53,4611.03 C77.1 5949.6,4535.43 J10.5
CH3_LNA_IN: C70.2 U15.3 | length 216.5
  Top Layer w10: C70.2 4262.21,4535.43 U15.3
CH3_LNA_OUT: C73.1 L17.2 U15.1 | length 438.9
  Top Layer w10: U15.1 4419.37,4509.84 4524.96,4615.43 4524.96,4625.43 ; L17.2 4489.47,4660.93 C73.1
CH3_SW_C: C70.1 U14.5 | length 233.1
  Top Layer w10: U14.5 3836.61,4548.15 3846.61,4538.15 4041.38,4538.15 C70.1
CH3_SW_RF1: C68.2 U14.1 | length 225.6
  Top Layer w10: U14.1 v1(3811.02,4532.72) ; v1(3831.02,4602.72) 3804.64,4629.1 3804.64,4666.89 C68.2
  Bottom Layer w10: v1(3811.02,4532.72) 3811.02,4582.72 v1(3831.02,4602.72)
CH3_SW_RF2: C67.2 U14.3 | length 274
  Top Layer w10: C67.2 3642.4,4532.01 v1(3742.2,4532.01) ; v1(3782.2,4492.01) 3802.2,4472.01 3852.2,4472.01 3862.2,4482.01 U14.3
  Bottom Layer w10: v1(3742.2,4532.01) v1(3782.2,4492.01)
CH4_ANT: C78.1 J11.5 | length 325.6
  Top Layer w10: J11.5 C78.1
CH4_CAL: C79.1 R25.2 | length 158.3
  Top Layer w10: C79.1 3864.64,4176.46 3864.64,4249.92 R25.2
  other v1: 3826.77,4279.53
CH4_F0: C84.2 C85.1 L22.1 | length 379
  Top Layer w10: C84.2 4735.63,4023.62 L22.1 4893.9,4099.01 C85.1
CH4_F2: C85.2 C86.1 L23.1 | length 379
  Top Layer w10: C85.2 5089.76,4023.62 C86.1 5247.83,4099.21 L23.1
CH4_F4: C87.1 L23.2 L24.1 | length 378.8
  Top Layer w10: L23.2 5437.2,4099.21 C87.1 5602.16,4099.21 L24.1
CH4_F6: C88.1 J12.5 L24.2 | length 1008.1
  Top Layer w10: L24.2 5791.53,4099.21 C88.1 5949.6,4023.62 J12.5
CH4_LNA_IN: C81.2 U17.3 | length 216.5
  Top Layer w10: C81.2 4262.21,4023.62 U17.3
CH4_LNA_OUT: C84.1 L21.2 U17.1 | length 408.8
  Top Layer w10: U17.1 4355.61,3998.03 4386.69,4029.11 4386.69,4079.11 L21.2 4582.19,4023.62 C84.1
CH4_SW_C: C81.1 U16.5 | length 266.5
  Top Layer w10: U16.5 3836.61,4077.05 3856.61,4097.05 3970.67,4097.05 C81.1
CH4_SW_RF1: C79.2 U16.1 | length 225.3
  Top Layer w10: U16.1 v1(3811.02,4020.9) ; v1(3831.02,4110.9) 3804.64,4137.28 3804.64,4154.25 C79.2
  In2.Cu w10: v1(3811.02,4020.9) 3811.02,4090.9 v1(3831.02,4110.9)
CH4_SW_RF2: C78.2 U16.3 | length 274
  Top Layer w10: C78.2 3642.4,4020.2 v1(3742.2,4020.2) ; v1(3782.2,3980.2) 3802.2,3960.2 3852.2,3960.2 3862.2,3970.2 U16.3
  In2.Cu w10: v1(3742.2,4020.2) v1(3782.2,3980.2)
CH5_ANT: C89.1 J13.5 | length 325.6
  Top Layer w10: J13.5 C89.1
CH5_CAL: C90.1 R26.2 | length 158.3
  Top Layer w10: C90.1 3864.64,3664.65 3864.64,3738.11 R26.2
  other v1: 3826.77,3767.72
CH5_F0: C95.2 C96.1 L26.1 | length 379
  Top Layer w10: C95.2 4735.63,3511.81 L26.1 4893.9,3587.2 C96.1
CH5_F2: C96.2 C97.1 L27.1 | length 379
  Top Layer w10: C96.2 5089.76,3511.81 C97.1 5247.83,3587.4 L27.1
CH5_F4: C98.1 L27.2 L28.1 | length 378.8
  Top Layer w10: L27.2 5437.2,3587.4 C98.1 5602.16,3587.4 L28.1
CH5_F6: C99.1 J14.5 L28.2 | length 1008.1
  Top Layer w10: L28.2 5791.53,3587.4 C99.1 5949.6,3511.81 J14.5
CH5_LNA_IN: C92.2 U19.3 | length 216.5
  Top Layer w10: C92.2 4262.21,3511.81 U19.3
CH5_LNA_OUT: C95.1 L25.2 U19.1 | length 438.9
  Top Layer w10: U19.1 4419.37,3486.22 4524.96,3591.81 4524.96,3601.81 ; L25.2 4489.47,3637.3 C95.1
CH5_SW_C: C92.1 U18.5 | length 233.1
  Top Layer w10: U18.5 3836.61,3524.53 3846.61,3514.53 4041.38,3514.53 C92.1
CH5_SW_RF1: C90.2 U18.1 | length 219.8
  Top Layer w10: U18.1 v1(3811.02,3509.09) ; v1(3831.02,3579.09) 3811.3,3598.82 3811.3,3649.09 C90.2
  Bottom Layer w10: v1(3811.02,3509.09) 3811.02,3559.09 v1(3831.02,3579.09)
CH5_SW_RF2: C89.2 U18.3 | length 409.7
  Top Layer w10: C89.2 3642.2,3508.58 3642.2,3418.39 3712.2,3348.39 3752.2,3348.39 3862.2,3458.39 U18.3
GND: C1.2 C2.2 C3.2 C4.2 C5.2 C6.2 C7.2 C8.2 C9.2 C10.2 C11.2 C12.2 C13.2 C14.2 C15.2 C16.2 C17.2 C18.2 C19.2 C20.2 C21.2 C23.2 C24.2 C27.2 C28.2 C31.2 C32.2 C36.2 C38.2 C39.2 C42.2 C43.2 C44.2 C47.2 C49.2 C50.2 C53.2 C54.2 C55.2 C58.2 C60.2 C61.2 C64.2 C65.2 C66.2 C69.2 C71.2 C72.2 C75.2 C76.2 C77.2 C80.2 C82.2 C83.2 C86.2 C87.2 C88.2 C91.2 C93.2 C94.2 C97.2 C98.2 C99.2 D2.1 D3.1 H1.1 H2.1 H3.1 H4.1 J1.2 J1.3 J2.2 J3.1 J3.2 J3.3 J3.4 J4.1 J4.2 J4.3 J4.4 J5.1 J5.2 J5.3 J5.4 J6.1 J6.2 J6.3 J6.4 J7.1 J7.2 J7.3 J7.4 J8.1 J8.2 J8.3 J8.4 J9.1 J9.2 J9.3 J9.4 J10.1 J10.2 J10.3 J10.4 J11.1 J11.2 J11.3 J11.4 J12.1 J12.2 J12.3 J12.4 J13.1 J13.2 J13.3 J13.4 J14.1 J14.2 J14.3 J14.4 L6.2 L10.2 L14.2 L18.2 L22.2 L26.2 R2.2 R4.2 R5.2 R6.2 R7.2 R9.2 R11.2 R12.2 R14.2 R15.2 R17.2 R18.2 R20.2 U1.6 U1.7 U1.8 U1.15 U1.16 U1.17 U2.9 U2.13 U3.9 U3.13 U4.2 U5.2 U5.4 U6.2 U6.4 U7.2 U7.4 U8.2 U9.2 U9.4 U10.2 U11.2 U11.4 U12.2 U13.2 U13.4 U14.2 U15.2 U15.4 U16.2 U17.2 U17.4 U18.2 U19.2 U19.4
  other v1: 3433.07,3255.91 3531.5,3255.91 3629.92,3255.91 3728.35,3255.91 3826.77,3255.91 3925.2,3255.91 4023.62,3255.91 4122.05,3255.91 4220.47,3255.91 4318.9,3255.91 4417.32,3255.91 4515.75,3255.91 4614.17,3255.91 4712.6,3255.91 4811.02,3255.91 4909.45,3255.91 5007.87,3255.91 5106.3,3255.91 5204.72,3255.91 5303.15,3255.91 5401.57,3255.91 5500,3255.91 5598.43,3255.91 5696.85,3255.91 5795.28,3255.91 5893.7,3255.91 5992.13,3255.91 6090.55,3255.91 6188.98,3255.91 6287.4,3255.91 6385.83,3255.91 6484.25,3255.91 3433.07,3767.72 3531.5,3767.72 3629.92,3767.72 3728.35,3767.72 3925.2,3767.72 4023.62,3767.72 4122.05,3767.72 4220.47,3767.72 4318.9,3767.72 4417.32,3767.72 4515.75,3767.72 4614.17,3767.72 4712.6,3767.72 4811.02,3767.72 4909.45,3767.72 5007.87,3767.72 5106.3,3767.72 5204.72,3767.72 5303.15,3767.72 5401.57,3767.72 5500,3767.72 5598.43,3767.72 5696.85,3767.72 5795.28,3767.72 5893.7,3767.72 5992.13,3767.72 6090.55,3767.72 6188.98,3767.72 6287.4,3767.72 6385.83,3767.72 6484.25,3767.72 3433.07,4279.53 3531.5,4279.53 3629.92,4279.53 3728.35,4279.53 3925.2,4279.53 4023.62,4279.53 4122.05,4279.53 4220.47,4279.53 4318.9,4279.53 4417.32,4279.53 4515.75,4279.53 4614.17,4279.53 4712.6,4279.53 4811.02,4279.53 4909.45,4279.53 5007.87,4279.53 5106.3,4279.53 5204.72,4279.53 5303.15,4279.53 5401.57,4279.53 5500,4279.53 5598.43,4279.53 5696.85,4279.53 5795.28,4279.53 5893.7,4279.53 5992.13,4279.53 6090.55,4279.53 6188.98,4279.53 6287.4,4279.53 6385.83,4279.53 6484.25,4279.53 3433.07,4791.34 3531.5,4791.34 3629.92,4791.34 3728.35,4791.34 3925.2,4791.34 4023.62,4791.34 4122.05,4791.34 4220.47,4791.34 4318.9,4791.34 4417.32,4791.34 4515.75,4791.34 4614.17,4791.34 4712.6,4791.34 4811.02,4791.34 4909.45,4791.34 5007.87,4791.34 5106.3,4791.34 5204.72,4791.34 5303.15,4791.34 5401.57,4791.34 5500,4791.34 5598.43,4791.34 5696.85,4791.34 5795.28,4791.34 5893.7,4791.34 5992.13,4791.34 6090.55,4791.34 6188.98,4791.34 6287.4,4791.34 6385.83,4791.34 6484.25,4791.34 3433.07,5303.15 3531.5,5303.15 3629.92,5303.15 3728.35,5303.15 3925.2,5303.15 4023.62,5303.15 4122.05,5303.15 4220.47,5303.15 4318.9,5303.15 4417.32,5303.15 4515.75,5303.15 4614.17,5303.15 4712.6,5303.15 4811.02,5303.15 4909.45,5303.15 5007.87,5303.15 5106.3,5303.15 5204.72,5303.15 5303.15,5303.15 5401.57,5303.15 5500,5303.15 5598.43,5303.15 5696.85,5303.15 5795.28,5303.15 5893.7,5303.15 5992.13,5303.15 6090.55,5303.15 6188.98,5303.15 6287.4,5303.15 6385.83,5303.15 6484.25,5303.15 3433.07,5814.96 3531.5,5814.96 3629.92,5814.96 3728.35,5814.96 3925.2,5814.96 4023.62,5814.96 4122.05,5814.96 4220.47,5814.96 4318.9,5814.96 4417.32,5814.96 4515.75,5814.96 4614.17,5814.96 4712.6,5814.96 4811.02,5814.96 4909.45,5814.96 5007.87,5814.96 5106.3,5814.96 5204.72,5814.96 5303.15,5814.96 5401.57,5814.96 5500,5814.96 5598.43,5814.96 5696.85,5814.96 5795.28,5814.96 5893.7,5814.96 5992.13,5814.96 6090.55,5814.96 6188.98,5814.96 6287.4,5814.96 6385.83,5814.96 6484.25,5814.96 3433.07,6326.77 3531.5,6326.77 3629.92,6326.77 3728.35,6326.77 3925.2,6326.77 4023.62,6326.77 4122.05,6326.77 4220.47,6326.77 4318.9,6326.77 4417.32,6326.77 4515.75,6326.77 4614.17,6326.77 4712.6,6326.77 4811.02,6326.77 4909.45,6326.77 5007.87,6326.77 5106.3,6326.77 5204.72,6326.77 5303.15,6326.77 5401.57,6326.77 5500,6326.77 5598.43,6326.77 5696.85,6326.77 5795.28,6326.77 5893.7,6326.77 5992.13,6326.77 6090.55,6326.77 6188.98,6326.77 6287.4,6326.77 6385.83,6326.77 6484.25,6326.77
LDO_LNA_ILIM: R5.1 U2.6 | length 2697.6
  Top Layer w10: R5.1 3953.82,7045.55 3970.68,7045.55 v1(4000.68,7015.55) ; v1(5300.67,6975.55) 5370.67,6905.55 5950.67,6905.55 6087.44,7042.32 6377.44,7042.32 6397.44,7062.32 U2.6
  In2.Cu w10: v1(4000.68,7015.55) 4070.68,6945.55 4280.67,6945.55 4350.67,7015.55 4393.27,7015.55 4433.27,6975.55 v1(5300.67,6975.55)
LDO_LNA_SET: C9.1 R4.1 U2.8 | length 3009.8
  Top Layer w10: C9.1 3831.86,7053.71 3831.86,7260.12 3921.86,7350.12 6331.85,7350.12 6371.85,7310.12 ; U2.8 6371.85,7310.12 ; R4.1 6428.31,7320.12 6381.85,7320.12 6371.85,7310.12
LDO_NS_ILIM: R7.1 U3.6 | length 405.5
  Top Layer w10: U3.6 4702.36,6823.62 R7.1
LDO_NS_SET: C14.1 R6.1 U3.8 | length 281.8
  Top Layer w10: U3.8 4542.72,7040.83 4552.72,7050.83 4602.72,7050.83 R6.1@4634.45,7019.1 ; R6.1 R6.1@4634.45,7019.1 ; C14.1 4737.72,6989.1 4664.45,6989.1 R6.1@4634.45,7019.1
LED_CAL: D3.2 R10.2 | length 2742.4
  Top Layer w10: D3.2 3864.98,6710.51 3974.98,6710.51 4004.98,6740.51 4004.98,6760.51 4214.98,6970.51 v1(4264.98,6970.51) ; v1(6384.97,6990.51) 6384.97,6995.6 R10.2
  In2.Cu w10: v1(4264.98,6970.51) 4274.98,6970.51 4334.98,7030.51 6344.97,7030.51 v1(6384.97,6990.51)
LED_PWR: D2.2 R8.2 | length 161.5
  Top Layer w10: R8.2 5882.16,7035.32 5973.25,7035.32 D2.2
NS_A0_IN: C22.2 U5.3 | length 143.5
  Top Layer w10: C22.2 4381.77,6625.32 4434.57,6625.32 U5.3@4468.7,6659.45
NS_A0_OUT: C25.1 L2.2 U5.1 | length 373.9
  Top Layer w10: U5.1 4417.52,6586.52 4436.79,6567.25 4486.79,6567.25 4496.79,6577.25 v1(4496.79,6634.69) ; v1(4576.79,6614.69) L2.2 4617.42,6655.32 C25.1
  In2.Cu w10: v1(4496.79,6634.69) 4516.79,6614.69 v1(4576.79,6614.69)
NS_A1_IN: C26.2 U6.3 | length 143.5
  Top Layer w10: C26.2 5185.31,6625.32 5238.11,6625.32 U6.3@5272.24,6659.45
NS_A1_OUT: C29.1 L3.2 U6.1 | length 325.2
  Top Layer w10: U6.1 5221.06,6583.96 5237.78,6567.25 5332.89,6567.25 L3.2 5420.96,6655.32 C29.1
NS_A2_IN: C30.2 U7.3 | length 143.5
  Top Layer w10: C30.2 5988.86,6625.32 6041.66,6625.32 U7.3@6075.79,6659.45
NS_A2_OUT: C33.1 L4.2 U7.1 | length 322.2
  Top Layer w10: U7.1 6024.61,6589.08 6046.44,6567.25 6136.44,6567.25 L4.2 6224.51,6655.32 C33.1
NS_P0_A: C25.2 R12.1 R13.1 | length 201.8
  Top Layer w10: C25.2 4791.93,6655.32 R12.1 4822.32,6684.92 4870.59,6684.92 R13.1
NS_P0_B: C26.1 R13.2 R14.1 | length 201.5
  Top Layer w10: R13.2 R14.1 5038.46,6625.32 5087.52,6625.32 C26.1
NS_P1_A: C29.2 R15.1 R16.1 | length 201.8
  Top Layer w10: C29.2 5595.47,6655.32 R15.1 5625.86,6624.92 5674.13,6624.92 R16.1
NS_P1_B: C30.1 R16.2 R17.1 | length 201.5
  Top Layer w10: R16.2 R17.1 5842.01,6625.32 5891.06,6625.32 C30.1
NS_P2_A: C33.2 R18.1 R19.1 | length 201.8
  Top Layer w10: C33.2 6399.02,6655.32 R18.1 6429.41,6624.92 6477.68,6624.92 R19.1
NS_P2_B: R19.2 R20.1 R21.1 R22.1 R23.1 R24.1 R25.1 R26.1 | length 7039.8
  Top Layer w10: v1(3827.55,5240.48) R23.1@3827.55,5270.48 ; R26.1 3830.08,3727.95 3794.64,3763.39 3794.64,3893.39 v1(3834.64,3933.39) ; R25.1 3828.27,4239.76 3794.64,4273.39 3794.64,4403.39 v1(3834.64,4443.39) ; R24.1 3826.45,4751.58 3794.64,4783.39 3794.64,4913.39 v1(3834.64,4953.39) ; R23.1 R23.1@3827.55,5270.48 ; R22.1 3825.2,5775.2 3799.92,5800.48 3799.92,5820.48 3819.92,5840.48 4039.92,5840.48 4269.92,6070.48 4309.92,6070.48 4319.92,6080.48 4319.92,6150.47 4289.92,6180.47 4289.92,6267.01 ; R21.1 4269.92,6287.01 4289.92,6267.01 ; 4049.92,5850.48 4289.92,5610.48 4309.92,5610.48 4319.92,5600.48 4319.92,5570.48 4309.92,5560.48 4239.92,5560.48 4009.92,5330.48 3819.92,5330.48 3799.92,5310.48 3799.92,5290.48 3819.92,5270.48 R23.1@3827.55,5270.48 ; v1(4399.92,6287.01) 4309.92,6287.01 4289.92,6267.01 ; v1(4459.92,6287.01) 6189.92,6287.01 6547.84,6644.92 R19.2 R20.1
  In2.Cu w10: v1(3827.55,5240.48) 3827.55,5004.26 3834.64,4997.17 v1(3834.64,4953.39) 3854.64,4933.39 3854.64,4514.65 3834.64,4494.65 v1(3834.64,4443.39) 3854.64,4423.39 3854.64,3953.39 v1(3834.64,3933.39) ; v1(4399.92,6287.01) v1(4459.92,6287.01)
NS_TERM: C22.1 R11.1 | length 133.4
  Top Layer w10: R11.1 4234.92,6625.32 4283.98,6625.32 C22.1
PG_5V6: R3.1 U1.4 | length 1815.8
  Top Layer w8.89: U1.4 4523.33,7139.96 4563.33,7099.96 4903.33,7099.96 5023.33,7219.96 5623.33,7219.96 5728.21,7324.84 6122.8,7324.84 R3.1
VIN_FUSED: D1.2 F1.2 | length 317.5
  Top Layer w10: F1.2 3926.18,7284.45 4136.81,7284.45 D1.2
VIN_RAW: F1.1 J1.1 | length 291.9
  Top Layer w10: J1.1 3679.13,7147.64 F1.1
pads on no net: U2.5 U3.5 U4.4

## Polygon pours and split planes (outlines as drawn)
+5V_LNA on In2.Cu (solid, remove dead copper): 3019.68,7389.76 6917.32,7389.76 6917.32,3019.68 3019.68,3019.68
GND on Top Layer (solid, remove dead copper, pour order 4): 3019.68,7389.76 6917.32,7389.76 6917.32,3019.68 3019.68,3019.68
GND on Bottom Layer (solid, remove dead copper, pour order 8): 3019.68,7389.76 6917.32,7389.76 6917.32,3019.68 3019.68,3019.68
GND on In1.Cu (solid, remove dead copper): 3019.68,7389.76 6917.32,7389.76 6917.32,3019.68 3019.68,3019.68

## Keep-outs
Board Outline Layer:
  the board outline again, w5.91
